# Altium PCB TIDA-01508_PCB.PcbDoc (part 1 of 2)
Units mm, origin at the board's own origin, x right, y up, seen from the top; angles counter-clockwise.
Board outline 58.5 x 103 mm, 4 copper layers (Top Layer, GND, VCC, Bottom Layer), stack 1.565 mm thick; 194 components, 119 nets, 642 pads, 130 vias.
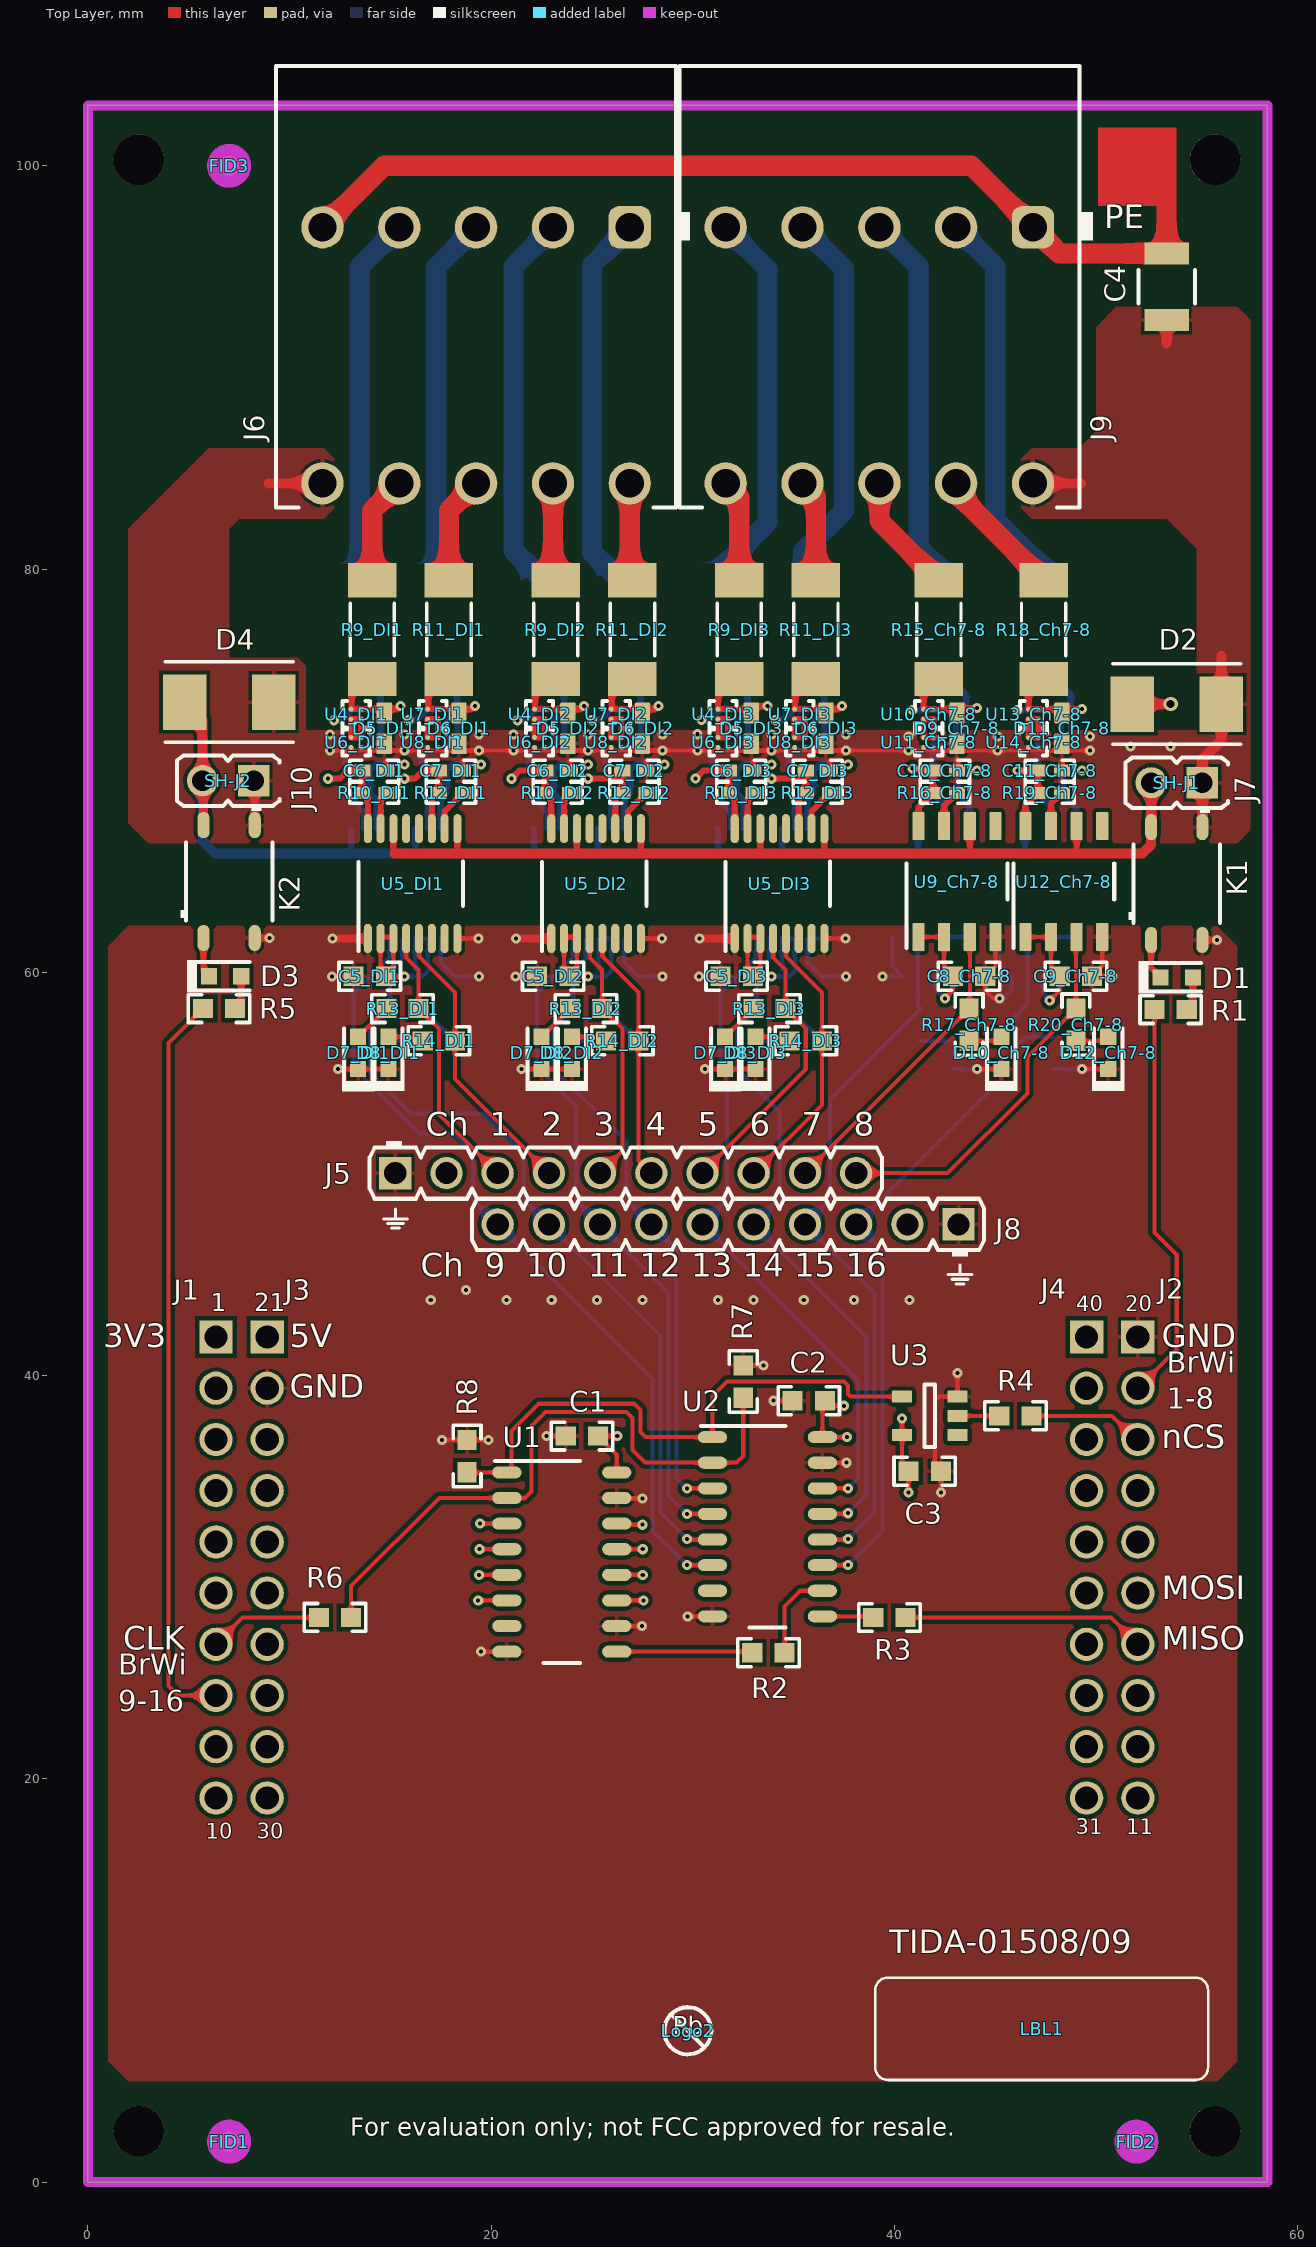
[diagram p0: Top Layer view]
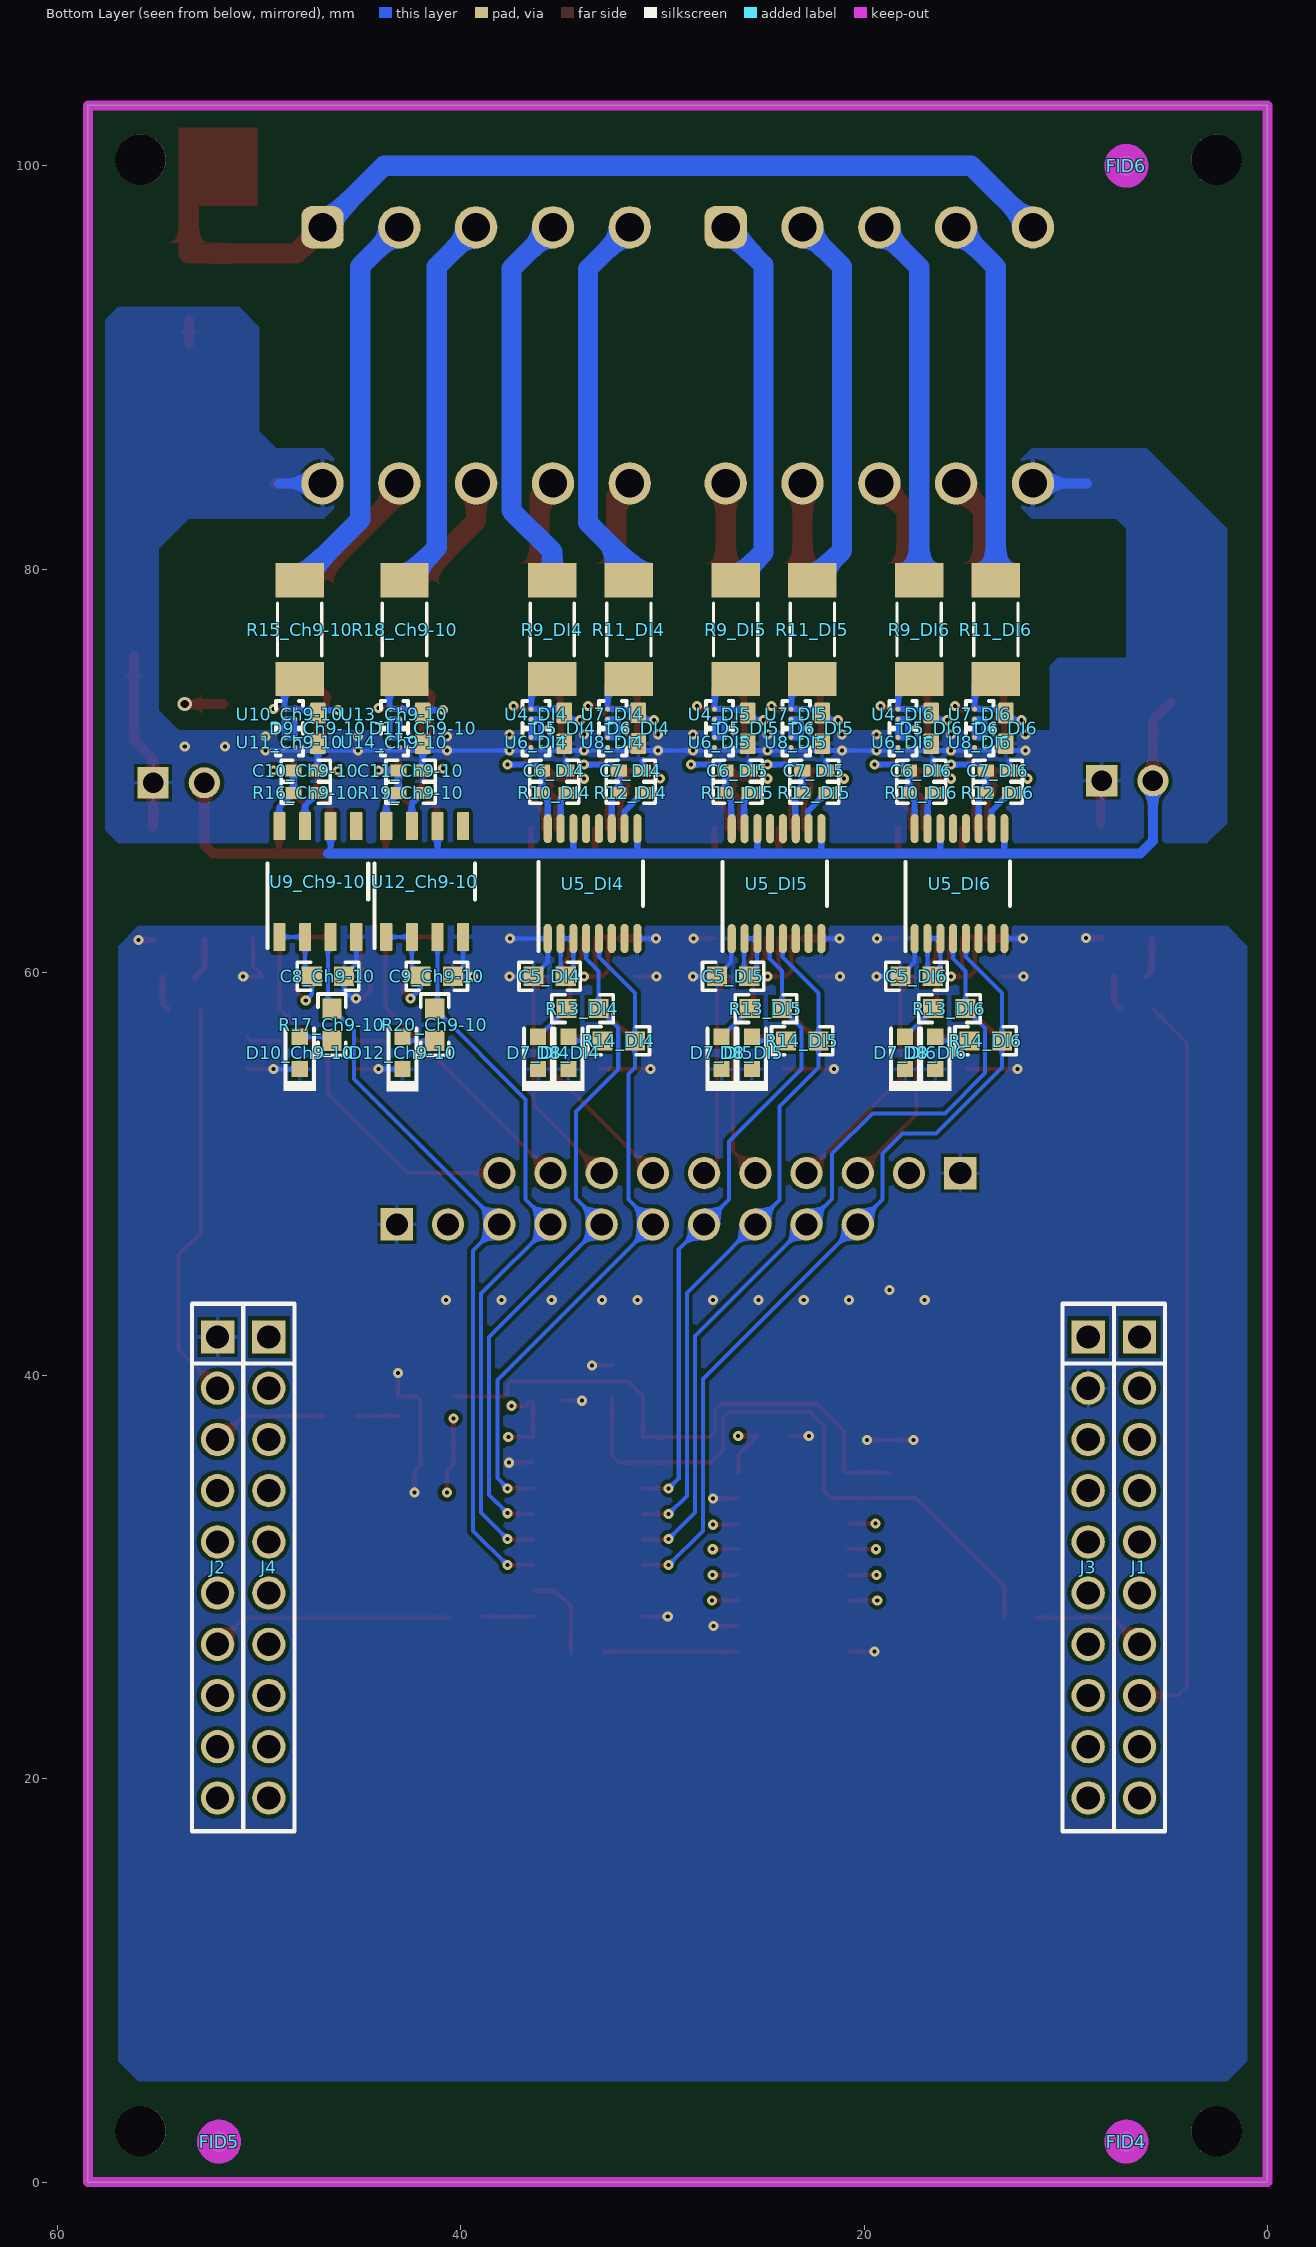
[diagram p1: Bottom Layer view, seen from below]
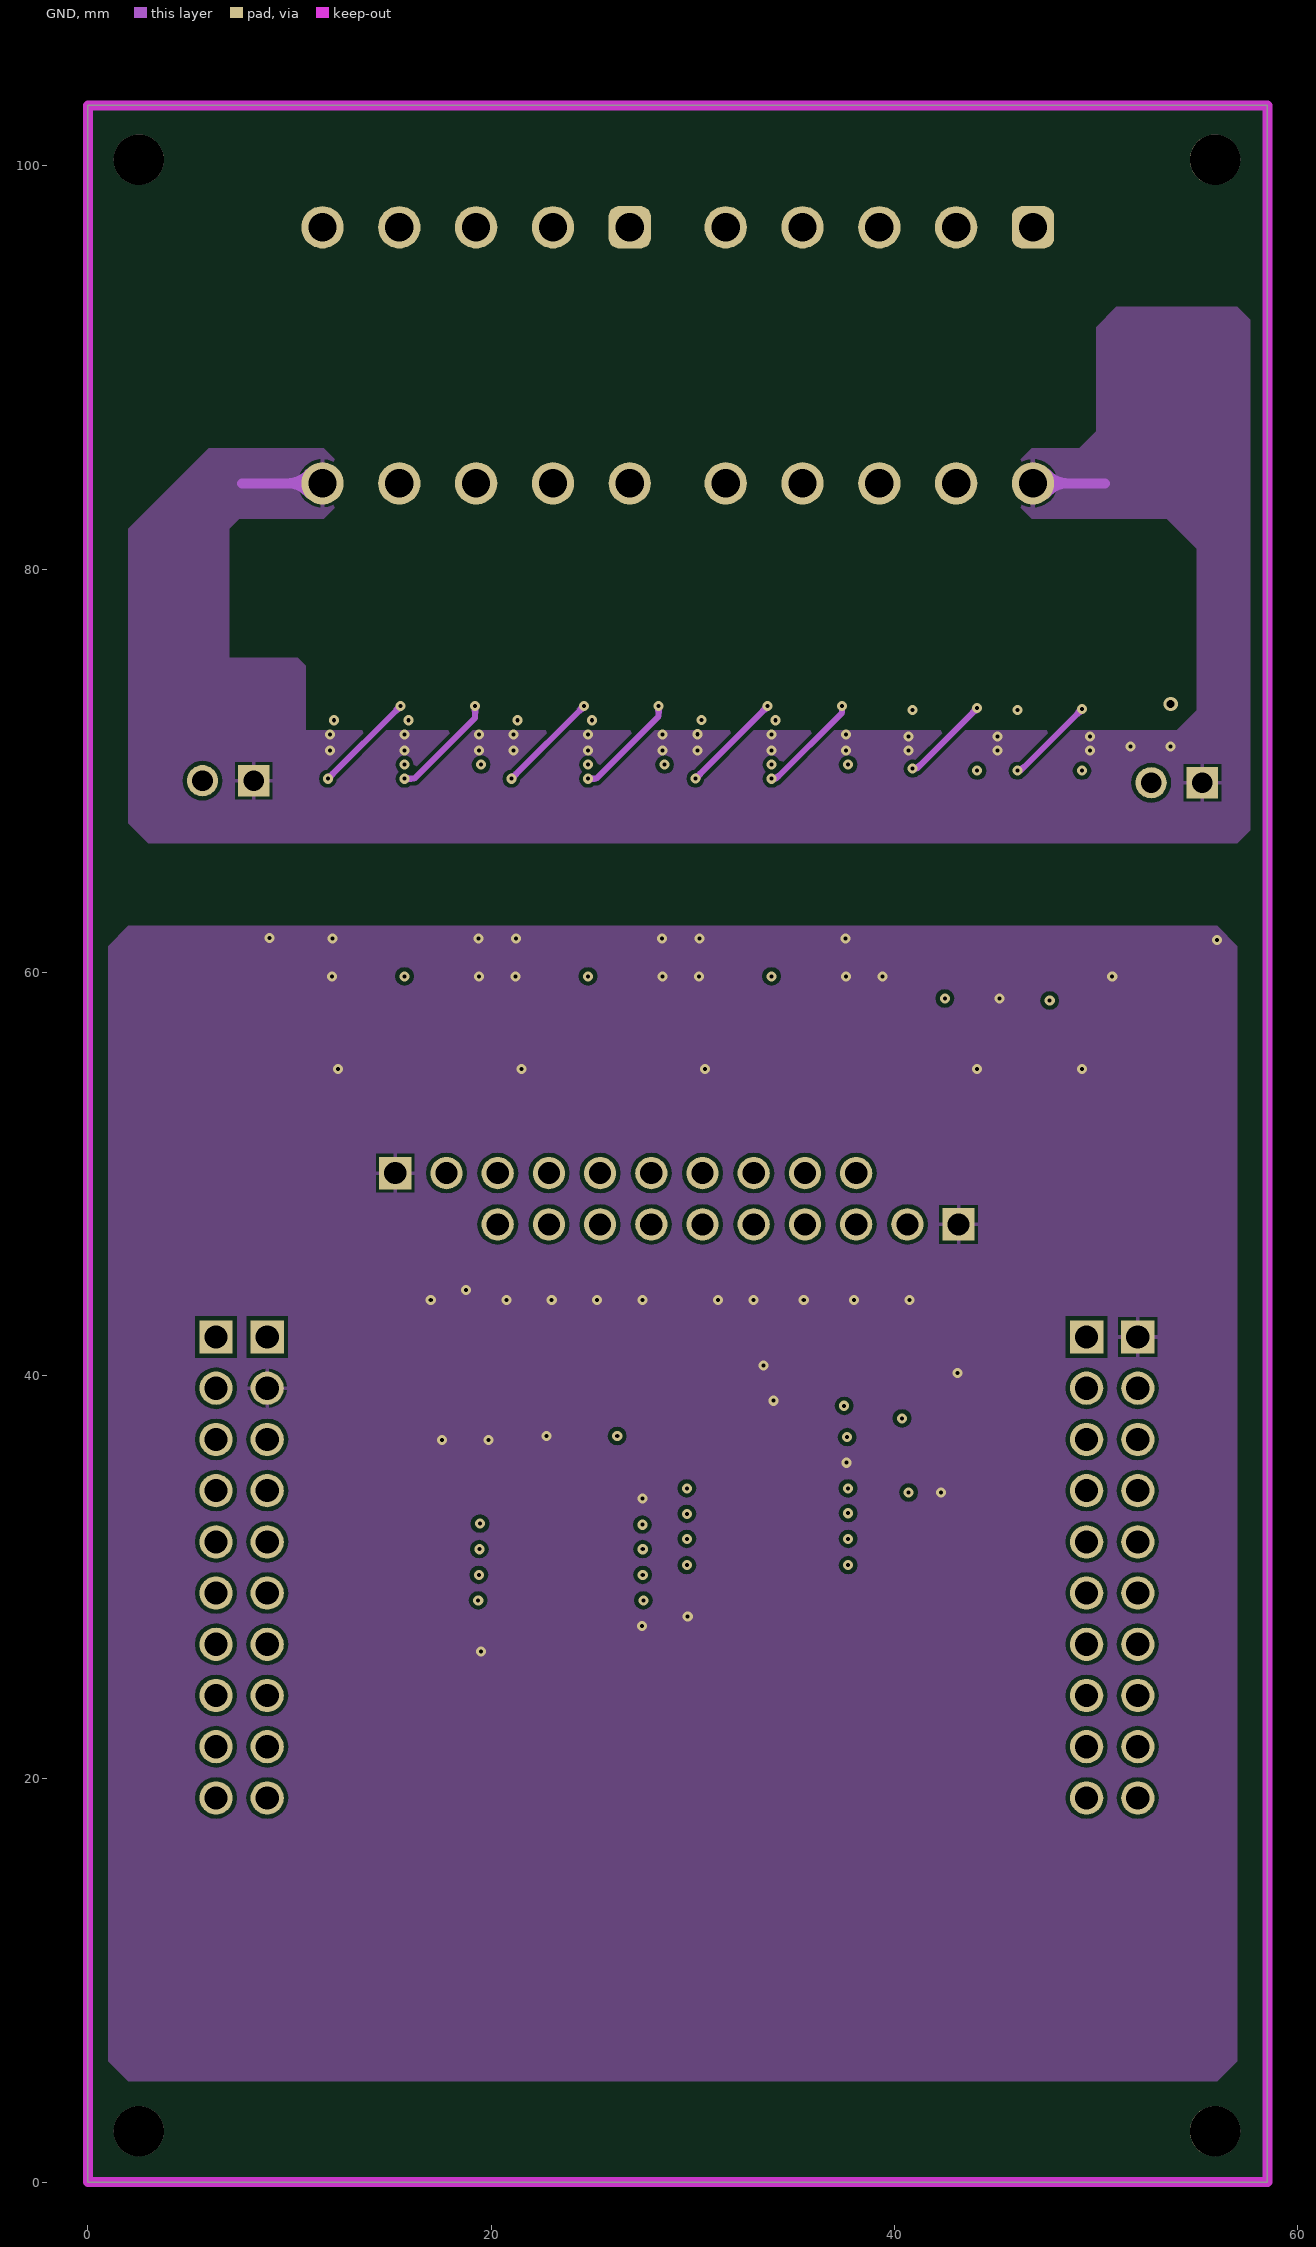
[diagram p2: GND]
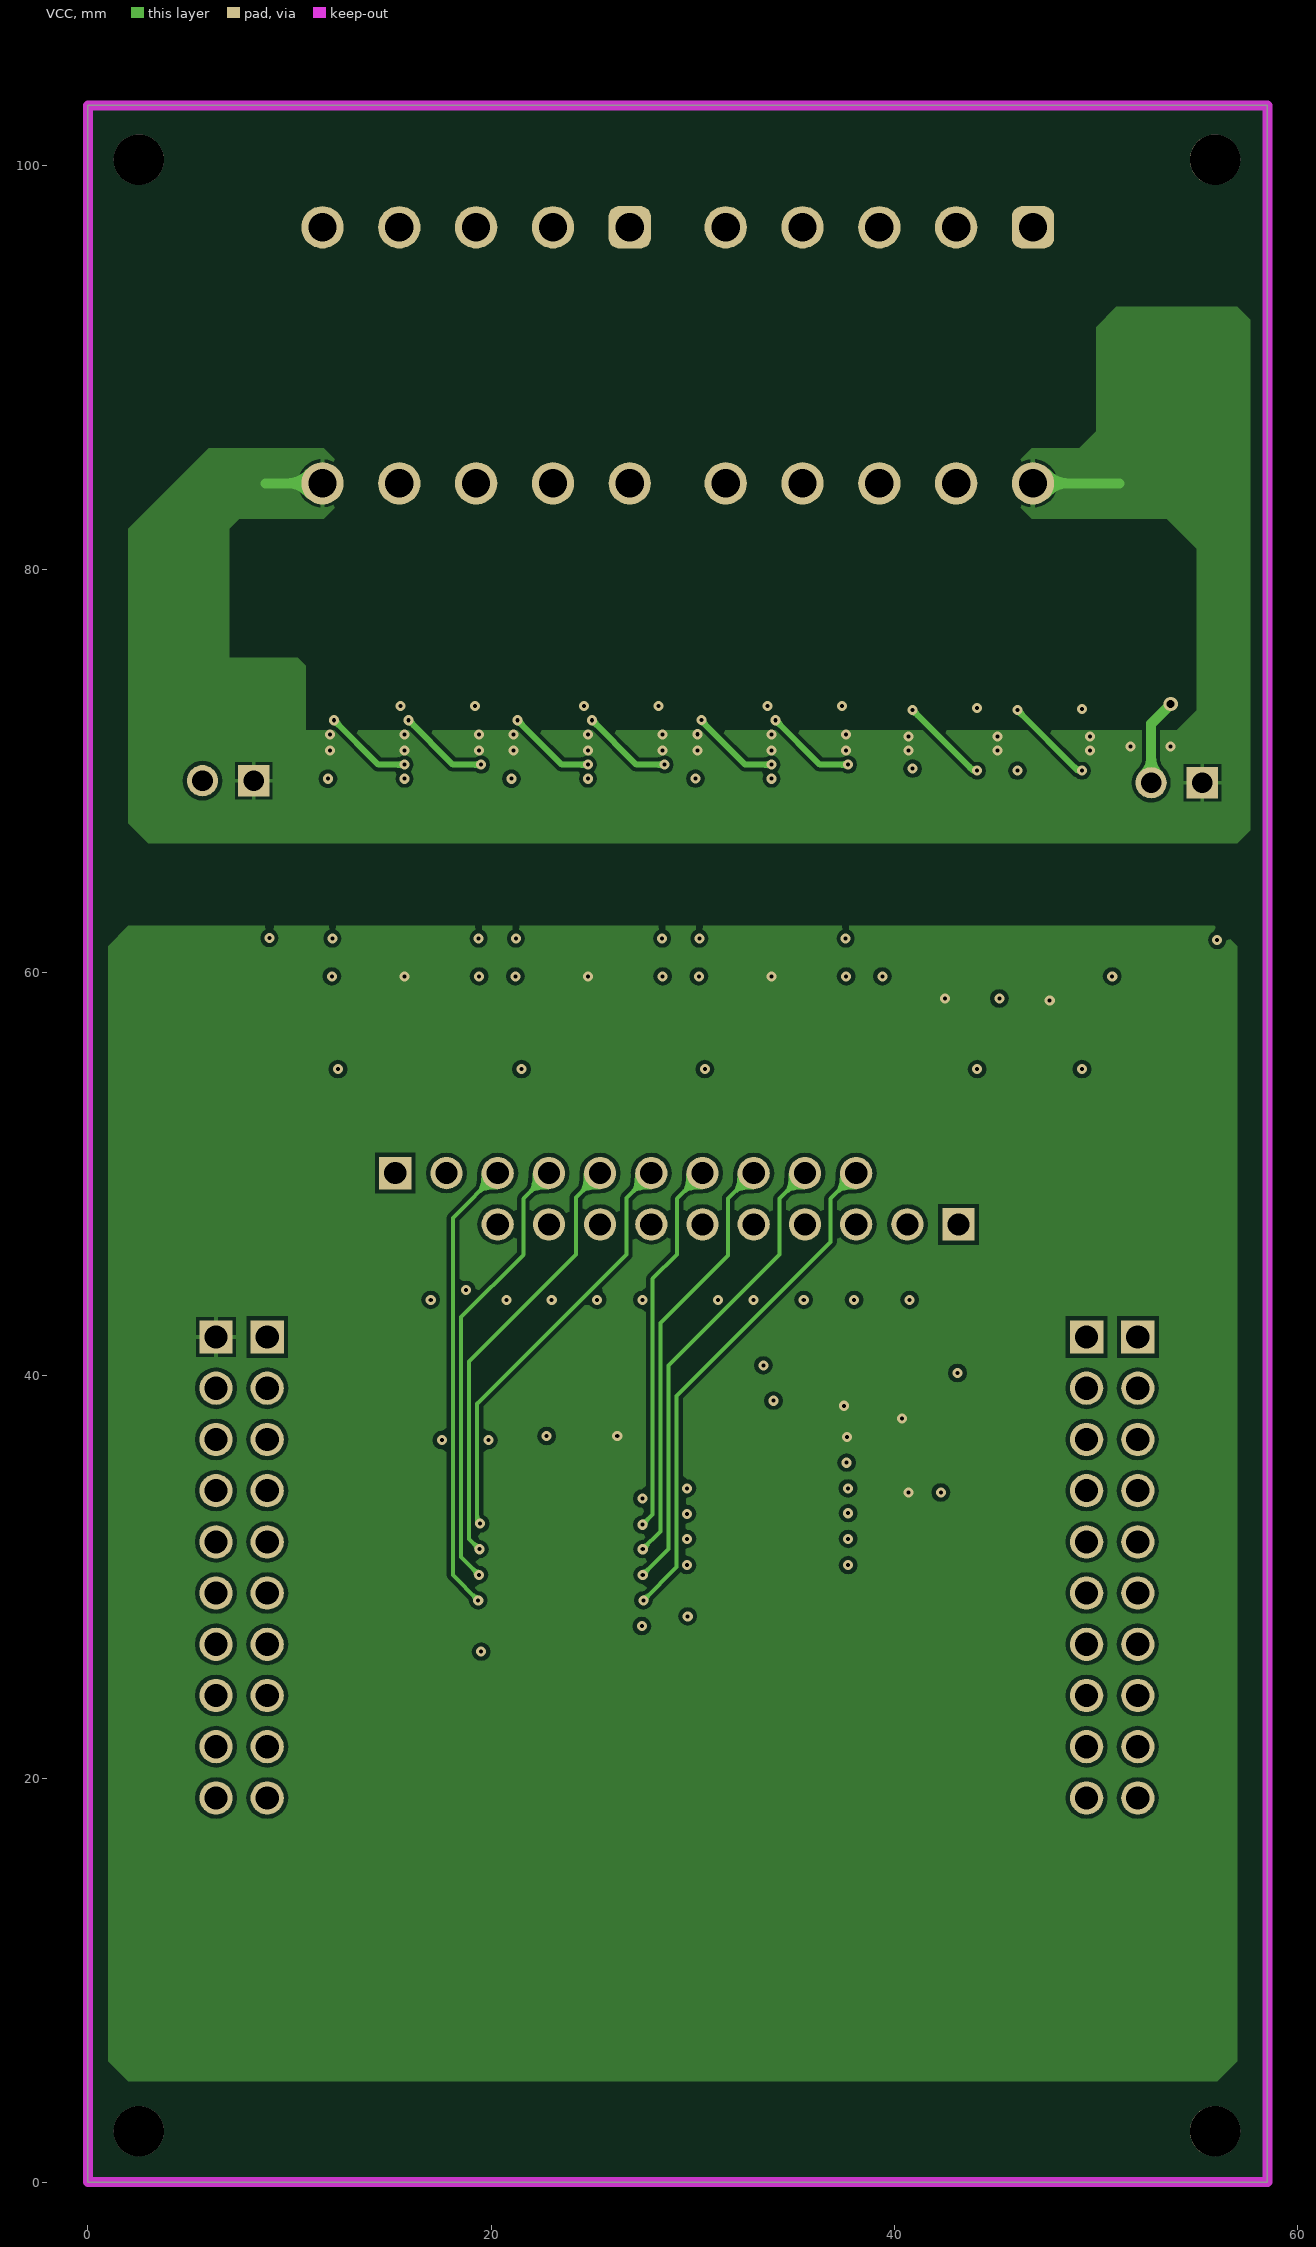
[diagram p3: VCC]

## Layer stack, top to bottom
Top Solder: solder mask 0.0102, Solder Resist, Dk 3.5
Top Layer: signal copper 0.0356
Dielectric 1: prepreg 0.2032, FR-4, Dk 4.2
GND: signal copper 0.0356
Dielectric 2: core 1.016, FR-4, Dk 4.2
VCC: signal copper 0.0356
Dielectric 3: prepreg 0.2032, FR-4, Dk 4.2
Bottom Layer: signal copper 0.0356
Bottom Solder: solder mask 0.0102, Solder Resist, Dk 3.5

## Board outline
0,0 0,103 58.5,103 58.5,0

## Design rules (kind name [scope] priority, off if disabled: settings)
AcuteAngle [All] p1: minimum=4.50000000000000E+0001 checktracksonly=FALSE
AssemblyTestPointUsage [All] p1: valid=2
Clearance Clearance_FID [IsKeepOut and InComponentClass('FiducialMark') vs IsPad and InComponentClass('FiducialMark')] p1: gap=0 ignorepadtopadclearanceinfootprint=FALSE
Clearance Clearance_Keepouts [((IsTrack Or IsArc) And Not InPoly) And IsFree and IsKeepOut vs ((IsTrack Or IsArc) And Not InPoly) And IsFree and IsKeepOut] p2: gap=0 ignorepadtopadclearanceinfootprint=FALSE
Clearance Clearance_BoardEdge_MountingHoles [OnCopper and InComponentClass('Mounting Holes') vs IsKeepOut] p3: gap=1 ignorepadtopadclearanceinfootprint=FALSE except(0: Arc-Hole Track-Hole SMDPad-Hole THPad-Hole Via-Hole Fill-Hole Poly-Hole Region-Hole Text-Hole)
Clearance Clearance_BoardEdge_Poly [OnCopper and InPoly vs IsKeepOut] p4: gap=0.6 ignorepadtopadclearanceinfootprint=FALSE except(0: Arc-Hole Track-Hole SMDPad-Hole THPad-Hole Via-Hole Fill-Hole Poly-Hole Region-Hole Text-Hole)
Clearance Clearance_BoardEdge [OnCopper and Not InComponentClass('Logo') and not InComponentClass('FiducialMark') and not InRegion(1000,500,4000,800) and Not IsKeepout vs IsKeepOut] p5: gap=0.635 ignorepadtopadclearanceinfootprint=FALSE except(0: Arc-Hole Track-Hole SMDPad-Hole THPad-Hole Via-Hole Fill-Hole Poly-Hole Region-Hole Text-Hole)
Clearance Clearance_Poly [InPolygon] p6: gap=0.2 ignorepadtopadclearanceinfootprint=FALSE except(0: Arc-Hole Track-Hole SMDPad-Hole THPad-Hole Via-Hole Fill-Hole Poly-Hole Region-Hole Text-Hole)
Clearance [All] p7: gap=0.15 ignorepadtopadclearanceinfootprint=FALSE except(0: Arc-Hole Track-Hole SMDPad-Hole THPad-Hole Via-Hole Fill-Hole Poly-Hole Region-Hole Text-Hole)
ComponentClearance ComponentClearance_Shunt [InComponentClass('Header') vs InComponentClass('Shunt')] p1: gap=0 collisioncheckmode=3 verticalgap=0 showdistances=FALSE
ComponentClearance ComponentClearance_Header2Header [InComponentClass('Header') vs InComponentClass('Header')] p2: gap=0 collisioncheckmode=3 verticalgap=0 showdistances=FALSE
ComponentClearance ComponentClearance_SmallPassives [HasFootprint('0201*') or HasFootprint('0402*') or HasFootprint('0508') or HasFootprint('0603*') or HasFootprint('0612') or HasFootprint('0805*') or HasFootprint('0815*') or HasFootprint('0830*') or HasFootprint('1206*') or HasFootprint('1210*') or HasFootprint('1808*') or HasFootprint('1812*') or HasFootprint('1825*') or HasFootprint('2010*') or HasFootprint('2220*') or HasFootprint('2225*') or HasFootprint('2512*') or HasFootprint('2728*') or HasFootprint('3518*') vs HasFootprint('0201*') or HasFootprint('0402*') or HasFootprint('0508') or HasFootprint('0603*') or HasFootprint('0612') or HasFootprint('0805*') or HasFootprint('0815*') or HasFootprint('0830*') or HasFootprint('1206*') or HasFootprint('1210*') or HasFootprint('1808*') or HasFootprint('1812*') or HasFootprint('1825*') or HasFootprint('2010*') or HasFootprint('2220*') or HasFootprint('2225*') or HasFootprint('2512*') or HasFootprint('2728*') or HasFootprint('3518*')] p3: gap=0.4 collisioncheckmode=3 verticalgap=0.254 showdistances=FALSE
ComponentClearance ComponentClearance_THtoSMT [IsThruComponent vs IsSMTComponent] p4: gap=0.5 collisioncheckmode=3 verticalgap=0.762 showdistances=FALSE
ComponentClearance ComponentClearance_MountingHoles_FiducialMarks [InComponentClass('Mounting Holes') vs InComponentClass('FiducialMark')] p5: gap=1.25 collisioncheckmode=3 verticalgap=0.254 showdistances=FALSE
ComponentClearance ComponentClearance_THtoTH [IsThruComponent vs IsThruComponent] p6: gap=1.25 collisioncheckmode=3 verticalgap=0.508 showdistances=FALSE
ComponentClearance ComponentClearance_Logo [InComponentClass('Logo')] p7: gap=1.25 collisioncheckmode=3 verticalgap=0.254 showdistances=FALSE
ComponentClearance [All] p8: gap=0.25 collisioncheckmode=3 verticalgap=0.25 showdistances=FALSE
DiffPairsRouting [All] p1: maxlimit=2.54 minlimit=0.254 mostfreqgap=0.254 toplayer_minwidth=0.381 toplayer_maxwidth=0.381 toplayer_prefwidth=0.381 midlayer1_minwidth=0.381 midlayer1_maxwidth=0.381 midlayer1_prefwidth=0.381 midlayer2_minwidth=0.381 midlayer2_maxwidth=0.381 midlayer2_prefwidth=0.381 bottomlayer_minwidth=0.381 bottomlayer_maxwidth=0.381 bottomlayer_prefwidth=0.381 maxuncoupledlength=25.4
FabricationTestPointUsage TestPointUsage [All] p1: valid=2 allowmultiple=FALSE
FabricationTestpoint Testpoint [All] p1: side=3 testpointundercomponent=TRUE minsize=1.016 maxsize=2.54 preferedsize=1.524 minholesize=0 maxholesize=1.016 preferedholesize=0.813 testpointgrid=0.025 allowsidetop=TRUE allowsidebottom=TRUE usegrid=TRUE gridtolerance=0
FanoutControl Fanout_LCC [IsLCC] p1: bgadir=Out bgaviamode=Centered fanoutstyle=Auto fanoutdirection=Alternating viagrid=0.025 // Fanout_LCC (Default Rule)
FanoutControl Fanout_BGA [IsBGA] p2: bgadir=Out bgaviamode=Centered fanoutstyle=Auto fanoutdirection=Alternating viagrid=0.025 // Fanout_BGA (Default Rule)
FanoutControl Fanout_Default [All] p4: bgadir=Out bgaviamode=Centered fanoutstyle=Auto fanoutdirection=Alternating viagrid=0.025 // Fanout_Default (Default Rule)
FanoutControl Fanout_Small [(CompPinCount < 5)] p5: bgadir=Out bgaviamode=Centered fanoutstyle=Auto fanoutdirection=OutThenIn viagrid=0.025 // Fanout_Small (Default Rule)
HoleSize [All] p1: absolutevalues=TRUE maxlimit=5 minlimit=0.2 maxpercent=80.000 minpercent=20.000
HoleToHoleClearance [All] p1: gap=0.25 allowstackedmicrovias=TRUE
MinimumAnnularRing MinimumAnnularRing_ThermalPadVias [IsVia and InAnyComponent] p1: minimumring=0.15
MinimumAnnularRing [All] p2: minimumring=0.15
MinimumSolderMaskSliver MinimumSolderMaskSliver_ISO121x [HasFootprint('DBQ0016A_N') vs HasFootprint('DBQ0016A_N')] p1: minsoldermaskwidth=0
MinimumSolderMaskSliver MinimumSolderMaskSliver_TVS3300 [HasFootprint('YZF0004-C01') vs HasFootprint('YZF0004-C01')] p2: minsoldermaskwidth=0
MinimumSolderMaskSliver MinimumSolderMaskSliver_Logo [InComponentClass('Logo') vs InComponentClass('Logo')] p3: minsoldermaskwidth=0.015
MinimumSolderMaskSliver [All] p4: minsoldermaskwidth=0.1
PlaneClearance [All] p1: clearance=0.5
PlaneConnect [All] p1: planeconnectstyle=Direct reliefexpansion=0.254 reliefentries=4 reliefconductorwidth=0.254 reliefairgap=0.254
PolygonConnect [All] p1: thpad.connectstyle=Relief thpad.reliefconductorwidth=0.2 thpad.reliefentries=4 thpad.polygonreliefangle="90 Angle" thpad.airgapwidth=0.15 smdpad.connectstyle=Relief smdpad.reliefconductorwidth=0.2 smdpad.reliefentries=4 smdpad.polygonreliefangle="90 Angle" smdpad.airgapwidth=0.15 via.connectstyle=Direct via.reliefconductorwidth=0.254 via.reliefentries=4 via.polygonreliefangle="90 Angle" via.airgapwidth=0.254
RoomDefinition DI5 [InComponentClass('DI5')] p1: confinementstyle=ConfineIn formatcopy=TRUE lockcomponents=TRUE outline 20.7,54 20.7,80.5 28.8,80.5 28.8,54
RoomDefinition DI6 [InComponentClass('DI6')] p2: confinementstyle=ConfineIn formatcopy=FALSE lockcomponents=TRUE outline 11.6,54 11.6,80.5 19.7,80.5 19.7,54
RoomDefinition DI4 [InComponentClass('DI4')] p3: confinementstyle=ConfineIn formatcopy=TRUE lockcomponents=TRUE outline 29.8,54 29.8,80.5 37.9,80.5 37.9,54
RoomDefinition DI2 [InComponentClass('DI2')] p4: confinementstyle=ConfineIn formatcopy=FALSE lockcomponents=TRUE outline 28.8,54 28.8,80.5 20.7,80.5 20.7,54
RoomDefinition DI3 [InComponentClass('DI3')] p5: confinementstyle=ConfineIn formatcopy=FALSE lockcomponents=TRUE outline 37.9,54 37.9,80.5 29.8,80.5 29.8,54
RoomDefinition DI1 [InComponentClass('DI1')] p6: confinementstyle=ConfineIn formatcopy=FALSE lockcomponents=TRUE outline 19.7,54 19.7,80.5 11.6,80.5 11.6,54
RoomDefinition Ch9-10 [InComponentClass('Ch9-10')] p7: confinementstyle=ConfineIn formatcopy=TRUE lockcomponents=FALSE outline 38.905,54 38.905,80.5 49.905,80.5 49.905,54
RoomDefinition Ch7-8 [InComponentClass('Ch7-8')] p8: confinementstyle=ConfineIn formatcopy=FALSE lockcomponents=FALSE outline 51.1,54 51.1,80.5 40.4,80.5 40.4,54
RoutingVias ThermalPadVias [IsVia and InAnyComponent] p1: holewidth=0.2 width=0.5 viastyle="Through Hole" minholewidth=0.2 minwidth=0.5 maxholewidth=1 maxwidth=1.3
RoutingVias [All] p2: holewidth=0.2 width=0.5 viastyle="Through Hole" minholewidth=0.2 minwidth=0.5 maxholewidth=0.5 maxwidth=0.8
ShortCircuit ShortCircuit_MH [InPadClass('MHclass')] p1: allowed=TRUE
ShortCircuit [All] p2: allowed=FALSE
SilkToBoardRegionClearance [Not ((IsComment or IsDesignator) And (Hide <> 'False')) and not InRegion(1000,500,4000,800)] p1:
SilkToSilkClearance SilkToSilkClearance_Pb-FreeLogo [(HasFootprint('Pb-Free_Overlay_Medium') OR HasFootprint('Pb-Free_Overlay_Small')) vs (HasFootprint('Pb-Free_Overlay_Medium') OR HasFootprint('Pb-Free_Overlay_Small'))] p1 off: silktosilkclearance=0
SilkToSilkClearance [All] p2 off: silktosilkclearance=0.127
SilkToSolderMaskClearance "Silk to Solder Mask Opening" [All] p1 off: minsilkscreentomaskgap=0.025 clearancetoexposedcopper=FALSE
SolderMaskExpansion SolderMaskExpansion_Via [IsVia] p1: expansion=0.05 soldermaskfromhole=TRUE
SolderMaskExpansion [IsComponent and not IsVia] p2: expansion=0.05
Width [All] p1: maxlimit=1 minlimit=0.15 preferedwidth=0.2 checkconnectedcopper=TRUE
12 further rules are at their usual default settings.

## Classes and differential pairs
channel class TIDA-01508_ISO1212: DI1 DI2 DI3 DI4 DI5 DI6
channel class TIDA-01508_ISO1211: Ch7-8 Ch9-10
component class Shunt: SH-J1 SH-J2
component class LaunchPadInterface: J1 J2 J3 J4
component class InputStage: C1 C2 C3 C4 D1 D2 D3 D4 J5 J6 J7 J8 J9 J10 K1 K2 R1 R2 R3 R4 R5 R6 R7 R8 SH-J1 SH-J2 U1 U2 U3
component class Header: J1 J2 J3 J4 J5 J6 J7 J8 J9 J10
component class DI6: C5_DI6 C6_DI6 C7_DI6 D5_DI6 D6_DI6 D7_DI6 D8_DI6 R9_DI6 R10_DI6 R11_DI6 R12_DI6 R13_DI6 R14_DI6 U4_DI6 U5_DI6 U6_DI6 U7_DI6 U8_DI6
component class DI5: C5_DI5 C6_DI5 C7_DI5 D5_DI5 D6_DI5 D7_DI5 D8_DI5 R9_DI5 R10_DI5 R11_DI5 R12_DI5 R13_DI5 R14_DI5 U4_DI5 U5_DI5 U6_DI5 U7_DI5 U8_DI5
component class DI4: C5_DI4 C6_DI4 C7_DI4 D5_DI4 D6_DI4 D7_DI4 D8_DI4 R9_DI4 R10_DI4 R11_DI4 R12_DI4 R13_DI4 R14_DI4 U4_DI4 U5_DI4 U6_DI4 U7_DI4 U8_DI4
component class DI3: C5_DI3 C6_DI3 C7_DI3 D5_DI3 D6_DI3 D7_DI3 D8_DI3 R9_DI3 R10_DI3 R11_DI3 R12_DI3 R13_DI3 R14_DI3 U4_DI3 U5_DI3 U6_DI3 U7_DI3 U8_DI3
component class DI2: C5_DI2 C6_DI2 C7_DI2 D5_DI2 D6_DI2 D7_DI2 D8_DI2 R9_DI2 R10_DI2 R11_DI2 R12_DI2 R13_DI2 R14_DI2 U4_DI2 U5_DI2 U6_DI2 U7_DI2 U8_DI2
component class DI1: C5_DI1 C6_DI1 C7_DI1 D5_DI1 D6_DI1 D7_DI1 D8_DI1 R9_DI1 R10_DI1 R11_DI1 R12_DI1 R13_DI1 R14_DI1 U4_DI1 U5_DI1 U6_DI1 U7_DI1 U8_DI1
component class Ch9-10: C8_Ch9-10 C9_Ch9-10 C10_Ch9-10 C11_Ch9-10 D9_Ch9-10 D10_Ch9-10 D11_Ch9-10 D12_Ch9-10 R15_Ch9-10 R16_Ch9-10 R17_Ch9-10 R18_Ch9-10 R19_Ch9-10 R20_Ch9-10 U9_Ch9-10 U10_Ch9-10 U11_Ch9-10 U12_Ch9-10 U13_Ch9-10 U14_Ch9-10
component class Ch7-8: C8_Ch7-8 C9_Ch7-8 C10_Ch7-8 C11_Ch7-8 D9_Ch7-8 D10_Ch7-8 D11_Ch7-8 D12_Ch7-8 R15_Ch7-8 R16_Ch7-8 R17_Ch7-8 R18_Ch7-8 R19_Ch7-8 R20_Ch7-8 U9_Ch7-8 U10_Ch7-8 U11_Ch7-8 U12_Ch7-8 U13_Ch7-8 U14_Ch7-8
component class Hardware: FID1 FID2 FID3 FID4 FID5 FID6 LBL1 Logo2 Logo3 ZZ1 ZZ2 ZZ3 ZZ4
component class FiducialMark: FID1 FID2 FID3 FID4 FID5 FID6
component class AssemblyNote: ZZ1 ZZ2 ZZ3 ZZ4
component class Label: LBL1

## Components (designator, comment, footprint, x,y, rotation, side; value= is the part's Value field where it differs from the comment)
C1 "GRM188R71H104KA93D" 0603 24.5,37 r180 top value=0.1uF
C2 "GRM188R71H104KA93D" 0603 35.75,38.75 r180 top value=0.1uF
C3 "GRM188R71H104KA93D" 0603 41.5,35.25 r0 top value=0.1uF
C4 "202S41W222KV4E" 1210_280 53.5,94 r90 top value=2200pF
C5_DI1 "GRM188R71H104KA93D" 0603 13.975,59.8 r180 top value=0.1uF (schematic designator C5)
C5_DI2 "GRM188R71H104KA93D" 0603 23.075,59.8 r180 top value=0.1uF (schematic designator C5)
C5_DI3 "GRM188R71H104KA93D" 0603 32.175,59.8 r180 top value=0.1uF (schematic designator C5)
C5_DI4 "GRM188R71H104KA93D" 0603 35.6,59.8 r0 bottom value=0.1uF (schematic designator C5)
C5_DI5 "GRM188R71H104KA93D" 0603 26.5,59.8 r0 bottom value=0.1uF (schematic designator C5)
C5_DI6 "GRM188R71H104KA93D" 0603 17.4,59.8 r0 bottom value=0.1uF (schematic designator C5)
C6_DI1 "CGA2B3X7R1H103K050BB" 0402 14.2,70 r180 top value=0.01uF (schematic designator C6)
C6_DI2 "CGA2B3X7R1H103K050BB" 0402 23.3,70 r180 top value=0.01uF (schematic designator C6)
C6_DI3 "CGA2B3X7R1H103K050BB" 0402 32.4,70 r180 top value=0.01uF (schematic designator C6)
C6_DI4 "CGA2B3X7R1H103K050BB" 0402 35.375,70 r0 bottom value=0.01uF (schematic designator C6)
C6_DI5 "CGA2B3X7R1H103K050BB" 0402 26.275,70 r0 bottom value=0.01uF (schematic designator C6)
C6_DI6 "CGA2B3X7R1H103K050BB" 0402 17.175,70 r0 bottom value=0.01uF (schematic designator C6)
C7_DI1 "CGA2B3X7R1H103K050BB" 0402 18,70 r180 top value=0.01uF (schematic designator C7)
C7_DI2 "CGA2B3X7R1H103K050BB" 0402 27.1,70 r180 top value=0.01uF (schematic designator C7)
C7_DI3 "CGA2B3X7R1H103K050BB" 0402 36.2,70 r180 top value=0.01uF (schematic designator C7)
C7_DI4 "CGA2B3X7R1H103K050BB" 0402 31.575,70 r0 bottom value=0.01uF (schematic designator C7)
C7_DI5 "CGA2B3X7R1H103K050BB" 0402 22.475,70 r0 bottom value=0.01uF (schematic designator C7)
C7_DI6 "CGA2B3X7R1H103K050BB" 0402 13.375,70 r0 bottom value=0.01uF (schematic designator C7)
C8_Ch7-8 "GRM188R71H104KA93D" 0603 43.7,59.8 r0 top value=0.1uF (schematic designator C8)
C8_Ch9-10 "GRM188R71H104KA93D" 0603 46.6,59.8 r180 bottom value=0.1uF (schematic designator C8)
C9_Ch7-8 "GRM188R71H104KA93D" 0603 49,59.8 r0 top value=0.1uF (schematic designator C9)
C9_Ch9-10 "GRM188R71H104KA93D" 0603 41.2,59.8 r180 bottom value=0.1uF (schematic designator C9)
C10_Ch7-8 "CGA2B3X7R1H103K050BB" 0402 42.5,70 r180 top value=0.01uF (schematic designator C10)
C10_Ch9-10 "CGA2B3X7R1H103K050BB" 0402 47.7,70 r0 bottom value=0.01uF (schematic designator C10)
C11_Ch7-8 "CGA2B3X7R1H103K050BB" 0402 47.7,70 r180 top value=0.01uF (schematic designator C11)
C11_Ch9-10 "CGA2B3X7R1H103K050BB" 0402 42.5,70 r0 bottom value=0.01uF (schematic designator C11)
D1 "150060RS75000" WL-SMCW_RED 54,59.75 r0 top value=Red
D2 "SM6T36CA" SMB-Bi 54,73.3 r180 top value=36V
D3 "150060RS75000" WL-SMCW_RED 6.8,59.8 r0 top value=Red
D4 "SM6T36CA" SMB-Bi 7,73.4 r180 top value=36V
D5_DI1 "CGA0603MLA-31900E" Bourns_CGA0603MLA 14.7,72.1 r90 top (schematic designator D5)
D5_DI2 "CGA0603MLA-31900E" Bourns_CGA0603MLA 23.8,72.1 r90 top (schematic designator D5)
D5_DI3 "CGA0603MLA-31900E" Bourns_CGA0603MLA 32.9,72.1 r90 top (schematic designator D5)
D5_DI4 "CGA0603MLA-31900E" Bourns_CGA0603MLA 34.875,72.1 r90 bottom (schematic designator D5)
D5_DI5 "CGA0603MLA-31900E" Bourns_CGA0603MLA 25.775,72.1 r90 bottom (schematic designator D5)
D5_DI6 "CGA0603MLA-31900E" Bourns_CGA0603MLA 16.675,72.1 r90 bottom (schematic designator D5)
D6_DI1 "CGA0603MLA-31900E" Bourns_CGA0603MLA 18.4,72.1 r90 top (schematic designator D6)
D6_DI2 "CGA0603MLA-31900E" Bourns_CGA0603MLA 27.5,72.1 r90 top (schematic designator D6)
D6_DI3 "CGA0603MLA-31900E" Bourns_CGA0603MLA 36.6,72.1 r90 top (schematic designator D6)
D6_DI4 "CGA0603MLA-31900E" Bourns_CGA0603MLA 31.202,72.106 r90 bottom (schematic designator D6)
D6_DI5 "CGA0603MLA-31900E" Bourns_CGA0603MLA 22.075,72.1 r90 bottom (schematic designator D6)
D6_DI6 "CGA0603MLA-31900E" Bourns_CGA0603MLA 12.975,72.1 r90 bottom (schematic designator D6)
D7_DI1 "150060YS75000" WL-SMCW_YELLOW 13.4,56 r90 top value=Yellow (schematic designator D7)
D7_DI2 "150060YS75000" WL-SMCW_YELLOW 22.5,56 r90 top value=Yellow (schematic designator D7)
D7_DI3 "150060YS75000" WL-SMCW_YELLOW 31.6,56 r90 top value=Yellow (schematic designator D7)
D7_DI4 "150060YS75000" WL-SMCW_YELLOW 36.175,56 r90 bottom value=Yellow (schematic designator D7)
D7_DI5 "150060YS75000" WL-SMCW_YELLOW 27.075,56 r90 bottom value=Yellow (schematic designator D7)
D7_DI6 "150060YS75000" WL-SMCW_YELLOW 17.975,56 r90 bottom value=Yellow (schematic designator D7)
D8_DI1 "150060YS75000" WL-SMCW_YELLOW 14.9,56 r90 top value=Yellow (schematic designator D8)
D8_DI2 "150060YS75000" WL-SMCW_YELLOW 24,56 r90 top value=Yellow (schematic designator D8)
D8_DI3 "150060YS75000" WL-SMCW_YELLOW 33.1,56 r90 top value=Yellow (schematic designator D8)
D8_DI4 "150060YS75000" WL-SMCW_YELLOW 34.675,56 r90 bottom value=Yellow (schematic designator D8)
D8_DI5 "150060YS75000" WL-SMCW_YELLOW 25.575,56 r90 bottom value=Yellow (schematic designator D8)
D8_DI6 "150060YS75000" WL-SMCW_YELLOW 16.475,56 r90 bottom value=Yellow (schematic designator D8)
D9_Ch7-8 "CGA0603MLA-31900E" Bourns_CGA0603MLA 43.1,72.1 r90 top (schematic designator D9)
D9_Ch9-10 "CGA0603MLA-31900E" Bourns_CGA0603MLA 47.1,72.1 r90 bottom (schematic designator D9)
D10_Ch7-8 "150060YS75000" WL-SMCW_YELLOW 45.3,56 r90 top value=Yellow (schematic designator D10)
D10_Ch9-10 "150060YS75000" WL-SMCW_YELLOW 48,56 r90 bottom value=Yellow (schematic designator D10)
D11_Ch7-8 "CGA0603MLA-31900E" Bourns_CGA0603MLA 48.3,72.1 r90 top (schematic designator D11)
D11_Ch9-10 "CGA0603MLA-31900E" Bourns_CGA0603MLA 41.9,72.1 r90 bottom (schematic designator D11)
D12_Ch7-8 "150060YS75000" WL-SMCW_YELLOW 50.6,56 r90 top value=Yellow (schematic designator D12)
D12_Ch9-10 "150060YS75000" WL-SMCW_YELLOW 42.9,56 r90 bottom value=Yellow (schematic designator D12)
FID1 "Fiducial" Fiducial10-20 7,2 r0 top
FID2 "Fiducial" Fiducial10-20 52,2 r0 top
FID3 "Fiducial" Fiducial10-20 7,100 r0 top
FID4 "Fiducial" Fiducial10-20 7,2 r180 bottom
FID5 "Fiducial" Fiducial10-20 52,2 r180 bottom
FID6 "Fiducial" Fiducial10-20 7,100 r180 bottom
J1 "SSW-110-23-F-S" CONN_SSW-110-23-F-S 6.35,30.48 r90 bottom locked
J2 "SSW-110-23-F-S" CONN_SSW-110-23-F-S 52.07,30.48 r90 bottom locked
J3 "SSW-110-23-F-S" CONN_SSW-110-23-F-S 8.89,30.48 r90 bottom locked
J4 "SSW-110-23-F-S" CONN_SSW-110-23-F-S 49.53,30.48 r90 bottom locked
J5 "61301011121" Wurth_61301011121 26.67,50.038 r0 top
J6 "691356310010B" Wurth_691356310010B 19.25,90.6 r270 top
J7 "0022284023" Molex_0022284023 54,69.4 r180 top
J8 "61301011121" Wurth_61301011121 31.75,47.498 r180 top
J9 "691356310010B" Wurth_691356310010B 39.25,90.6 r270 top
J10 "0022284023" Molex_0022284023 6.95,69.5 r180 top
K1 "CPC1117N" RELAY_CPC1017N 54,64.4 r90 top
K2 "CPC1117N" RELAY_CPC1017N 7,64.5 r90 top
LBL1 "Size: 0.65\" x 0.20 \"" Label_650x200 47.3,7.6 r0 top
Logo2 "Pb-Free Symbol" Pb-Free_Overlay_Small 29.75,7.5 r0 top
Logo3 "FCC disclaimer" FCC_disclaimer 149,19.75 r90 top
R1 "CRCW0603100RFKEA" 0603 53.7,58.15 r0 top value=100
R2 "CRCW060347R0JNEA" 0603 33.75,26.25 r180 top value=47
R3 "CRCW060347R0JNEA" 0603 39.75,28 r180 top value=47
R4 "CRCW06030000Z0EA" 0603 46,38 r180 top value=0
R5 "CRCW0603100RFKEA" 0603 6.5,58.2 r0 top value=100
R6 "CRCW06030000Z0EA" 0603 12.25,28 r0 top value=0
R7 "CRCW0603100RFKEA" 0603 32.5,39.7 r270 top value=100
R8 "CRCW0603100RFKEA" 0603 18.8,36 r270 top value=100
R9_DI1 "MMB02070C2491FB200" MMB0207 14.1,77 r90 top value=2.49k (schematic designator R9)
R9_DI2 "MMB02070C2491FB200" MMB0207 23.2,77 r90 top value=2.49k (schematic designator R9)
R9_DI3 "MMB02070C2491FB200" MMB0207 32.3,77 r90 top value=2.49k (schematic designator R9)
R9_DI4 "MMB02070C2491FB200" MMB0207 35.475,77 r90 bottom value=2.49k (schematic designator R9)
R9_DI5 "MMB02070C2491FB200" MMB0207 26.375,77 r90 bottom value=2.49k (schematic designator R9)
R9_DI6 "MMB02070C2491FB200" MMB0207 17.275,77 r90 bottom value=2.49k (schematic designator R9)
R10_DI1 "CRCW0402562RFKED" 0402 14.2,68.9 r180 top value=562 (schematic designator R10)
R10_DI2 "CRCW0402562RFKED" 0402 23.3,68.9 r180 top value=562 (schematic designator R10)
R10_DI3 "CRCW0402562RFKED" 0402 32.4,68.9 r180 top value=562 (schematic designator R10)
R10_DI4 "CRCW0402562RFKED" 0402 35.375,68.9 r0 bottom value=562 (schematic designator R10)
R10_DI5 "CRCW0402562RFKED" 0402 26.275,68.9 r0 bottom value=562 (schematic designator R10)
R10_DI6 "CRCW0402562RFKED" 0402 17.175,68.9 r0 bottom value=562 (schematic designator R10)
R11_DI1 "MMB02070C2491FB200" MMB0207 17.9,77 r90 top value=2.49k (schematic designator R11)
R11_DI2 "MMB02070C2491FB200" MMB0207 27,77 r90 top value=2.49k (schematic designator R11)
R11_DI3 "MMB02070C2491FB200" MMB0207 36.1,77 r90 top value=2.49k (schematic designator R11)
R11_DI4 "MMB02070C2491FB200" MMB0207 31.675,77 r90 bottom value=2.49k (schematic designator R11)
R11_DI5 "MMB02070C2491FB200" MMB0207 22.575,77 r90 bottom value=2.49k (schematic designator R11)
R11_DI6 "MMB02070C2491FB200" MMB0207 13.475,77 r90 bottom value=2.49k (schematic designator R11)
R12_DI1 "CRCW0402562RFKED" 0402 18,68.9 r180 top value=562 (schematic designator R12)
R12_DI2 "CRCW0402562RFKED" 0402 27.1,68.9 r180 top value=562 (schematic designator R12)
R12_DI3 "CRCW0402562RFKED" 0402 36.2,68.9 r180 top value=562 (schematic designator R12)
R12_DI4 "CRCW0402562RFKED" 0402 31.575,68.9 r0 bottom value=562 (schematic designator R12)
R12_DI5 "CRCW0402562RFKED" 0402 22.475,68.9 r0 bottom value=562 (schematic designator R12)
R12_DI6 "CRCW0402562RFKED" 0402 13.375,68.9 r0 bottom value=562 (schematic designator R12)
R13_DI1 "CRCW0603750RFKEA" 0603 15.6,58.2 r0 top value=750 (schematic designator R13)
R13_DI2 "CRCW0603750RFKEA" 0603 24.7,58.2 r0 top value=750 (schematic designator R13)
R13_DI3 "CRCW0603750RFKEA" 0603 33.8,58.2 r0 top value=750 (schematic designator R13)
R13_DI4 "CRCW0603750RFKEA" 0603 33.975,58.2 r180 bottom value=750 (schematic designator R13)
R13_DI5 "CRCW0603750RFKEA" 0603 24.875,58.2 r180 bottom value=750 (schematic designator R13)
R13_DI6 "CRCW0603750RFKEA" 0603 15.775,58.2 r180 bottom value=750 (schematic designator R13)
R14_DI1 "CRCW0603750RFKEA" 0603 17.4,56.6 r0 top value=750 (schematic designator R14)
R14_DI2 "CRCW0603750RFKEA" 0603 26.5,56.6 r0 top value=750 (schematic designator R14)
R14_DI3 "CRCW0603750RFKEA" 0603 35.6,56.6 r0 top value=750 (schematic designator R14)
R14_DI4 "CRCW0603750RFKEA" 0603 32.175,56.6 r180 bottom value=750 (schematic designator R14)
R14_DI5 "CRCW0603750RFKEA" 0603 23.075,56.6 r180 bottom value=750 (schematic designator R14)
R14_DI6 "CRCW0603750RFKEA" 0603 13.975,56.6 r180 bottom value=750 (schematic designator R14)
R15_Ch7-8 "MMB02070C2491FB200" MMB0207 42.2,77 r90 top value=2.49k (schematic designator R15)
R15_Ch9-10 "MMB02070C2491FB200" MMB0207 48,77 r90 bottom value=2.49k (schematic designator R15)
R16_Ch7-8 "CRCW0402562RFKED" 0402 42.5,68.9 r180 top value=562 (schematic designator R16)
R16_Ch9-10 "CRCW0402562RFKED" 0402 47.7,68.9 r0 bottom value=562 (schematic designator R16)
R17_Ch7-8 "CRCW0603750RFKEA" 0603 43.7,57.4 r90 top value=750 (schematic designator R17)
R17_Ch9-10 "CRCW0603750RFKEA" 0603 46.4,57.4 r90 bottom value=750 (schematic designator R17)
R18_Ch7-8 "MMB02070C2491FB200" MMB0207 47.4,77 r90 top value=2.49k (schematic designator R18)
R18_Ch9-10 "MMB02070C2491FB200" MMB0207 42.8,77 r90 bottom value=2.49k (schematic designator R18)
R19_Ch7-8 "CRCW0402562RFKED" 0402 47.7,68.9 r180 top value=562 (schematic designator R19)
R19_Ch9-10 "CRCW0402562RFKED" 0402 42.5,68.9 r0 bottom value=562 (schematic designator R19)
R20_Ch7-8 "CRCW0603750RFKEA" 0603 49,57.4 r90 top value=750 (schematic designator R20)
R20_Ch9-10 "CRCW0603750RFKEA" 0603 41.3,57.4 r90 bottom value=750 (schematic designator R20)
SH-J1 "60900213421" Wurth_60900213421 54,69.4 r180 top
SH-J2 "60900213421" Wurth_60900213421 6.95,69.5 r180 top
U1 "SN74LV165AD" D0016A_N 23.5,30.75 r0 top
U2 "SN74LV165AD" D0016A_N 33.7,32.5 r0 top
U3 "SN74LVC1GU04DBVR" DBV0005A_N 41.75,38 r180 top
U4_DI1 "TVS3300YZFR" YZF0004-C01 13.3,72.8 r0 top (schematic designator U4)
U4_DI2 "TVS3300YZFR" YZF0004-C01 22.4,72.8 r0 top (schematic designator U4)
U4_DI3 "TVS3300YZFR" YZF0004-C01 31.5,72.8 r0 top (schematic designator U4)
U4_DI4 "TVS3300YZFR" YZF0004-C01 36.275,72.8 r180 bottom (schematic designator U4)
U4_DI5 "TVS3300YZFR" YZF0004-C01 27.175,72.8 r180 bottom (schematic designator U4)
U4_DI6 "TVS3300YZFR" YZF0004-C01 18.075,72.8 r180 bottom (schematic designator U4)
U5_DI1 "ISO1212DBQR" DBQ0016A_N 16.1,64.4 r90 top (schematic designator U5)
U5_DI2 "ISO1212DBQR" DBQ0016A_N 25.2,64.4 r90 top (schematic designator U5)
U5_DI3 "ISO1212DBQR" DBQ0016A_N 34.3,64.4 r90 top (schematic designator U5)
U5_DI4 "ISO1212DBQR" DBQ0016A_N 33.475,64.4 r90 bottom (schematic designator U5)
U5_DI5 "ISO1212DBQR" DBQ0016A_N 24.348,64.394 r90 bottom (schematic designator U5)
U5_DI6 "ISO1212DBQR" DBQ0016A_N 15.275,64.4 r90 bottom (schematic designator U5)
U6_DI1 "TVS3300YZFR" YZF0004-C01 13.3,71.4 r180 top (schematic designator U6)
U6_DI2 "TVS3300YZFR" YZF0004-C01 22.4,71.4 r180 top (schematic designator U6)
U6_DI3 "TVS3300YZFR" YZF0004-C01 31.5,71.4 r180 top (schematic designator U6)
U6_DI4 "TVS3300YZFR" YZF0004-C01 36.275,71.4 r0 bottom (schematic designator U6)
U6_DI5 "TVS3300YZFR" YZF0004-C01 27.175,71.4 r0 bottom (schematic designator U6)
U6_DI6 "TVS3300YZFR" YZF0004-C01 18.075,71.4 r0 bottom (schematic designator U6)
U7_DI1 "TVS3300YZFR" YZF0004-C01 17.1,72.8 r0 top (schematic designator U7)
U7_DI2 "TVS3300YZFR" YZF0004-C01 26.2,72.8 r0 top (schematic designator U7)
U7_DI3 "TVS3300YZFR" YZF0004-C01 35.3,72.8 r0 top (schematic designator U7)
U7_DI4 "TVS3300YZFR" YZF0004-C01 32.475,72.8 r180 bottom (schematic designator U7)
U7_DI5 "TVS3300YZFR" YZF0004-C01 23.375,72.8 r180 bottom (schematic designator U7)
U7_DI6 "TVS3300YZFR" YZF0004-C01 14.275,72.8 r180 bottom (schematic designator U7)
U8_DI1 "TVS3300YZFR" YZF0004-C01 17.1,71.4 r180 top (schematic designator U8)
U8_DI2 "TVS3300YZFR" YZF0004-C01 26.2,71.4 r180 top (schematic designator U8)
U8_DI3 "TVS3300YZFR" YZF0004-C01 35.3,71.4 r180 top (schematic designator U8)
U8_DI4 "TVS3300YZFR" YZF0004-C01 32.475,71.4 r0 bottom (schematic designator U8)
U8_DI5 "TVS3300YZFR" YZF0004-C01 23.375,71.4 r0 bottom (schematic designator U8)
U8_DI6 "TVS3300YZFR" YZF0004-C01 14.275,71.4 r0 bottom (schematic designator U8)
U9_Ch7-8 "ISO1211DR" D0008B_HV 43.1,64.5 r90 top (schematic designator U9)
U9_Ch9-10 "ISO1211DR" D0008B_HV 47.1,64.5 r90 bottom (schematic designator U9)
U10_Ch7-8 "TVS3300YZFR" YZF0004-C01 41.7,72.8 r0 top (schematic designator U10)
U10_Ch9-10 "TVS3300YZFR" YZF0004-C01 48.5,72.8 r180 bottom (schematic designator U10)
U11_Ch7-8 "TVS3300YZFR" YZF0004-C01 41.7,71.4 r180 top (schematic designator U11)
U11_Ch9-10 "TVS3300YZFR" YZF0004-C01 48.5,71.4 r0 bottom (schematic designator U11)
U12_Ch7-8 "ISO1211DR" D0008B_HV 48.4,64.5 r90 top (schematic designator U12)
U12_Ch9-10 "ISO1211DR" D0008B_HV 41.8,64.5 r90 bottom (schematic designator U12)
U13_Ch7-8 "TVS3300YZFR" YZF0004-C01 46.9,72.8 r0 top (schematic designator U13)
U13_Ch9-10 "TVS3300YZFR" YZF0004-C01 43.3,72.8 r180 bottom (schematic designator U13)
U14_Ch7-8 "TVS3300YZFR" YZF0004-C01 46.9,71.4 r180 top (schematic designator U14)
U14_Ch9-10 "TVS3300YZFR" YZF0004-C01 43.3,71.4 r0 bottom (schematic designator U14)
ZZ1 "This Assembly Note is for PCB labels only" AssemblyNoteLabel 2.54,118.567 r0 top
ZZ2 "This Assembly Note will show in the PcbDoc and associated outputs" AssemblyNote 2.54,115.801 r0 top
ZZ3 "This Assembly Note will show in the PcbDoc and associated outputs" AssemblyNote 2.54,113.552 r0 top
ZZ4 "This Assembly Note will show in the PcbDoc and associated outputs" AssemblyNote 2.54,111.303 r0 top

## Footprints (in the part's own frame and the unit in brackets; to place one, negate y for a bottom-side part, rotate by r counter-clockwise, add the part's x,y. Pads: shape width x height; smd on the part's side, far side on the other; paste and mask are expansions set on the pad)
0402 [mm] "0402 from SM-752 data"
  rect 0.8x0.6 smd: 1(-0.6,0) 2(0.6,0)
  silkscreen extent -1.22,-0.52 1.22,0.52, body extent -0.55,-0.3 0.55,0.3, height 0.6
0603 [mm] "0603 from SM-752 data"
  rect 1x0.95 smd: 1(-0.8,0) 2(0.8,0)
  silkscreen extent -1.52,-0.69 1.52,0.69, body extent -0.87,-0.47 0.87,0.47, height 1
1210_280 [mm] "SMD, 2-Leads, Body 3.6x2.8mm, Height 2.8mm"
  rect 1.1x2.2 smd: 1(-1.65,0) 2(1.65,0)
  silkscreen extent -0.84,-1.4 0.84,1.4, body extent -1.8,-1.4 1.8,1.4, height 2.8
AssemblyNote [mm] "Assembly Note"
AssemblyNoteLabel [mm] "Assembly Note for PCB Labels"
Bourns_CGA0603MLA [mm] "SMD, 2-Leads, Body 1.6x0.8mm"
  rrect13% 1.02x0.76 smd: 1(-0.76,0) 2(0.76,0)
  body extent -0.8,-0.4 0.8,0.4, height 0.8
CONN_SSW-110-23-F-S [mm] "SAMTEC"
  rect 1.65x1.65 hole 1.15: 1(11.43,0)
  round 1.65 hole 1.15: 2(8.89,0) 3(6.35,0) 4(3.81,0) 5(1.27,0) 6(-1.27,0) 7(-3.81,0) 8(-6.35,0) 9(-8.89,0) 10(-11.43,0)
  silkscreen extent -13.08,-1.27 13.08,1.27, body extent -13,-1.27 13,1.27, height 8.59
D0008B_HV [mm] "SOIC, 8-Leads, Body 4.9x3.9mm, Pitch 1.27mm, HV / Isolation option"
  rrect17% 1.4x0.6 smd: 1(-2.75,1.905) 2(-2.75,0.635) 3(-2.75,-0.635) 4(-2.75,-1.905) 5(2.75,-1.905) 6(2.75,-0.635) 7(2.75,0.635) 8(2.75,1.905)
  silkscreen extent -3.3,-2.5 0.9,2.5, body extent -3,-2.45 3,2.45, height 1.63
D0016A_N [mm] "SOIC, 16-Leads, Body 9.9x3.9mm, Pitch 1.27mm, IPC Medium Density"
  oval 1.45x0.6 smd: 1(-2.725,4.445) 2(-2.725,3.175) 3(-2.725,1.905) 4(-2.725,0.635) 5(-2.725,-0.635) 6(-2.725,-1.905) 7(-2.725,-3.175) 8(-2.725,-4.445) 9(2.725,-4.445) 10(2.725,-3.175) 11(2.725,-1.905) 12(2.725,-0.635) 13(2.725,0.635) 14(2.725,1.905) 15(2.725,3.175) 16(2.725,4.445)
  silkscreen extent -3.3,-5 0.9,5, body extent -3,-4.95 3,4.95, height 1.6
DBQ0016A_N [mm] "SOP, 16-Leads, Body 4.9x3.9mm, Pitch 0.635mm, IPC Medium Density"
  oval 1.45x0.4 smd: 1(-2.725,2.222) 2(-2.725,1.587) 3(-2.725,0.952) 4(-2.725,0.317) 5(-2.725,-0.318) 6(-2.725,-0.953) 7(-2.725,-1.588) 8(-2.725,-2.222) 9(2.725,-2.222) 10(2.725,-1.587) 11(2.725,-0.952) 12(2.725,-0.317) 13(2.725,0.318) 14(2.725,0.953) 15(2.725,1.588) 16(2.725,2.222)
  silkscreen extent -3.35,-2.5 1.1,2.68, body extent -3.01,-2.45 3.01,2.45, height 1.63
DBV0005A_N [mm] "SOT23, 5-Leads, Body 2.9x1.6mm, Pitch 0.95mm, Lead Span 2.8mm, IPC Medium Density"
  rrect17% 1x0.6 smd: 1(-1.375,0.95) 2(-1.375,0) 3(-1.375,-0.95) 4(1.375,-0.95) 5(1.375,0.95)
  silkscreen extent -0.25,-1.55 0.25,1.55, body extent -1.42,-1.46 1.42,1.46, height 1.09
FCC_disclaimer [mm]
Fiducial10-20 [mm]
  round 1 smd mask+0.5: 1(0,0)
  Top Layer keep-out circle w1.178: c0,0 r0.5
Label_650x200 [mil] "Thermal Transfer Label"
  round 1 on Mech13: 0(0,0)
  silkscreen extent -325,-100 325,100, body extent -325,-100 325,100, height 1
MMB0207 [mm] "Vishay Beyschlag"
  rect 1.7x2.4 smd: 1(-2.45,0) 2(2.45,0)
  silkscreen extent -1.3,-1.1 1.3,1.1, body extent -2.98,-1.1 2.98,1.1, height 2.2
Molex_0022284023 [mm] "Header, 2.54mm, 2x1, TH"
  rect 1.55x1.55 hole 1.02: 1(-1.27,0)
  round 1.55 hole 1.02: 2(1.27,0)
  silkscreen extent -2.54,-1.24 2.54,1.5, body extent -2.54,-1.24 2.54,1.24, height 8.4
Pb-Free_Overlay_Small [mm]
  silkscreen extent -1.16,-1.17 1.17,1.17
RELAY_CPC1017N [mm] "SOP, 4-Lead, Body 4.089x3.81mm, Pitch 2.54mm"
  oval 1.3x0.6 smd: 1(-2.8,1.27) 2(-2.8,-1.27) 3(2.8,-1.27) 4(2.8,1.27)
  silkscreen extent -1.94,-2.15 1.94,2.4, body extent -1.94,-2.15 1.94,2.15, height 2.18
SMB-Bi [mm] "Molded Diode, 2-Leads, Body 5.4x3.6mm, IPC Medium Density, based on OnSemi component dimensions"
  rect 2.159x2.743 smd: 1(-2.21,0) 2(2.21,0)
  silkscreen extent -3.18,-1.99 3.18,1.99, body extent -2.65,-1.85 2.65,1.85, height 2.26
WL-SMCW_RED [mm] "WURTH"
  rect 0.8x0.8 smd: 1(-0.8,0) 2(0.8,0)
  silkscreen extent -1.9,-0.8 1.2,0.8, body extent -0.85,-0.45 0.85,0.45, height 0.8
WL-SMCW_YELLOW [mm] "WURTH"
  rect 0.8x0.8 smd: 1(-0.8,0) 2(0.8,0)
  silkscreen extent -1.9,-0.8 1.2,0.8, body extent -0.85,-0.45 0.85,0.45, height 0.8
Wurth_60900213421 [mil] "Shunt, 2.54mm, Black"
  round 1 on Mech3: 0(0,0)
  body extent -98,-48 98,48, height 236
Wurth_61301011121 [mm] "Header, 2.54mm, 10x1, TH"
  rect 1.6x1.6 hole 1.1: 1(-11.43,0)
  round 1.6 hole 1.1: 2(-8.89,0) 3(-6.35,0) 4(-3.81,0) 5(-1.27,0) 6(1.27,0) 7(3.81,0) 8(6.35,0) 9(8.89,0) 10(11.43,0)
  silkscreen extent -12.7,-1.27 12.7,1.6, body extent -12.7,-1.27 12.7,1.27, height 8.54
Wurth_691356310010B [mm] "Header, 3.81mm, 5x2, TH"
  rrect50% 2.1x2.1 hole 1.4: 1(-6.35,7.62)
  round 2.1 hole 1.4: 2(6.35,7.62) 3(-6.35,3.81) 4(6.35,3.81) 5(-6.35,0) 6(6.35,0) 7(-6.35,-3.81) 8(6.35,-3.81) 9(-6.35,-7.62) 10(6.35,-7.62)
  silkscreen extent -14.35,-9.92 7.55,10.6, body extent -14.35,-9.92 7.55,9.92, height 22.5
YZF0004-C01 [mm] "BGA, 4-Balls, Body 1.062x1.116mm, Pitch 0.5mm"
  round 0.245 smd paste-0.125: A1(-0.25,0.25) A2(0.25,0.25) B1(-0.25,-0.25) B2(0.25,-0.25)
  silkscreen extent -0.68,-0.65 0.67,0.65, body extent -0.57,-0.55 0.57,0.55, height 0.63

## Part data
C1 C2 C3 C5_DI1 C5_DI2 C5_DI3 C5_DI4 C5_DI5 C5_DI6 C8_Ch7-8 C8_Ch9-10 C9_Ch7-8 C9_Ch9-10: "CAP, CERM, 0.1 µF, 50 V,+/- 10%, X7R, 0603", Cap_Case=0603, Manufacturer=MuRata, Supplier Part Number 1=490-1519-1-ND, TempCo=X7R, Tolerance_%=10, Value2=50V, ValueDisplayed=0.1µF
C4: "CAP, CERM, 2200 pF, 2000 V,+/- 10%, X7R, 1210", Cap_Case=1210, Manufacturer="Johanson Technology", Supplier Part Number 1=709-1307-1-ND, TempCo=X7R, Tolerance_%=10, Value2=2000V, ValueDisplayed=2200pF
C6_DI1 C6_DI2 C6_DI3 C6_DI4 C6_DI5 C6_DI6 C7_DI1 C7_DI2 C7_DI3 C7_DI4 C7_DI5 C7_DI6 C10_Ch7-8 C10_Ch9-10 C11_Ch7-8 C11_Ch9-10: "CAP, CERM, 0.01 µF, 50 V,+/- 10%, X7R, AEC-Q200 Grade 1, 0402", Cap_Case=0402, Manufacturer=TDK, Supplier Part Number 1=445-6893-1-ND, TempCo=X7R, Tolerance_%=10, Value1="0.333065 ohm", Value2=50V, ValueDisplayed=0.01µF
D1 D3: "LED, Red, SMD", Color=Red, Manufacturer="Wurth Elektronik", Power_TotalModule=0.072, Supplier Part Number 1=732-4978-1-ND, Value1=0.072W, Value2=2V
D2 D4: "Diode, TVS, Bi, 36 V, 64.3 Vc, SMB", Manufacturer=STMicroelectronics, Supplier Part Number 1=497-6496-1-ND, Value1=W
D5_DI1 D5_DI2 D5_DI3 D5_DI4 D5_DI5 D5_DI6 D6_DI1 D6_DI2 D6_DI3 D6_DI4 D6_DI5 D6_DI6 D9_Ch7-8 D9_Ch9-10 D11_Ch7-8 D11_Ch9-10: library part CMP-0076768-1, "ChipGuard Automotive MLA Series Varistor ESD Clamp Protectors", Manufacturer=Bourns, Supplier Part Number 1=CGA0603MLA-31900E-ND
D7_DI1 D7_DI2 D7_DI3 D7_DI4 D7_DI5 D7_DI6 D8_DI1 D8_DI2 D8_DI3 D8_DI4 D8_DI5 D8_DI6 D10_Ch7-8 D10_Ch9-10 D12_Ch7-8 D12_Ch9-10: "LED, Yellow, SMD", Color=yellow, Manufacturer="Wurth Elektronik", Supplier Part Number 1=732-4981-1-ND, Value1=W, Value2=2V
FID1 FID2 FID3 FID4 FID5 FID6: "Fiducial mark.  There is nothing to buy or mount.", Manufacturer=N/A
J1 J2 J3 J4: "Connector, Receptacle, 100mil, 10x1, Gold plated, TH", Manufacturer=Samtec
J5 J8: "Header, 2.54mm, 10x1, Gold, TH", Color=Black, Manufacturer="Wurth Elektronik", Supplier Part Number 1=732-2670-ND
J6 J9: library part CMP-0077239-1, "Header, 3.81mm, 5x2, R/A, Tin, TH", Color="Light Green", Current_A=10A, Manufacturer="Wurth Elektronik", Voltage_V=300V
J7 J10: "Header, 2.54mm, 2x1, Tin, TH", Color=Black, Current_A=4, Manufacturer=Molex, Supplier Part Number 1=WM50016-02-ND, Voltage_V=250
K1 K2: "Relay, SPST-NC (1 Form B), 0.15 A, SMD", Contact Rating_A=0.15, Manufacturer=IXYS, Supplier Part Number 1=CPC1117N-ND
LBL1: library part THT-14-423-10, "Thermal Transfer Printable Labels, 0.650\" W x 0.200\" H - 10,000 per roll", Manufacturer=Brady, Supplier Part Number 1=97C5133
Logo2: library part Pb-Free
Logo3: library part FCC_disclaimer, "FCC_disclaimer"
R1 R5 R7 R8: "RES, 100, 1%, 0.1 W, 0603", Manufacturer=Vishay-Dale, Power_W=0.1, Supplier Part Number 1=541-100HCT-ND, TempCo="100 ppm/C", Tolerance_%=1, Value1=1%, Value2=0.1W, Value_Code=100R, ValueDisplayed=100
R2 R3: "RES, 47, 5%, 0.1 W, 0603", Manufacturer=Vishay-Dale, Power_W=0.1, Supplier Part Number 1=541-47GCT-ND, TempCo="200 ppm/C", Tolerance_%=5, Value1=5%, Value2=0.1W, Value_Code=47R0, ValueDisplayed=47
R4 R6: "RES, 0, 5%, 0.1 W, 0603", Manufacturer=Vishay-Dale, Power_W=0.1, Supplier Part Number 1=541-0.0GCT-ND, TempCo="200 ppm/C", Tolerance_%=5, Value1=5%, Value2=0.1W, Value_Code=0000, ValueDisplayed=0
R9_DI1 R9_DI2 R9_DI3 R9_DI4 R9_DI5 R9_DI6 R11_DI1 R11_DI2 R11_DI3 R11_DI4 R11_DI5 R11_DI6 R15_Ch7-8 R15_Ch9-10 R18_Ch7-8 R18_Ch9-10: library part CMP-0076703-1, "RES, 2.49 k, 1%, 1 W, AEC-Q200 Grade 0, 2.2x5.8mm", Manufacturer=Vishay/Beyschlag, Power_W=1W, Supplier Part Number 1=MMB-2.49KBCT-ND, TempCo="50 ppm/C", Tolerance_%=1%, Value_Code=2k49, ValueDisplayed=2.49k
R10_DI1 R10_DI2 R10_DI3 R10_DI4 R10_DI5 R10_DI6 R12_DI1 R12_DI2 R12_DI3 R12_DI4 R12_DI5 R12_DI6 R16_Ch7-8 R16_Ch9-10 R19_Ch7-8 R19_Ch9-10: "RES, 562, 1%, 0.063 W, 0402", Manufacturer=Vishay-Dale, Power_W=0.063, Supplier Part Number 1=541-562LCT-ND, TempCo="100 ppm/C", Tolerance_%=1, Value1=1%, Value2=0.063W, Value_Code=562R, ValueDisplayed=562
R13_DI1 R13_DI2 R13_DI3 R13_DI4 R13_DI5 R13_DI6 R14_DI1 R14_DI2 R14_DI3 R14_DI4 R14_DI5 R14_DI6 R17_Ch7-8 R17_Ch9-10 R20_Ch7-8 R20_Ch9-10: "RES, 750, 1%, 0.1 W, 0603", Manufacturer=Vishay-Dale, Power_W=0.1, Supplier Part Number 1=541-750HCT-ND, TempCo="100 ppm/C", Tolerance_%=1, Value1=1%, Value2=0.1W, Value_Code=750R, ValueDisplayed=750
SH-J1 SH-J2: "Shunt, 2.54mm, Gold, Black", Manufacturer="Wurth Elektronik", Supplier Part Number 1=732-2678-ND
U1 U2: "Parallel-Load 8-Bit Shift Registers, D0016A, TUBE", Alternate Manufacturer="Texas Instruments", Alternate PartNumber=Equivalent, F @ Nom Voltage(Max)(Mhz)=70, Generic Part Number=SN74LV165A, ICC @ Nom Voltage(Max)(mA)=0.02, Operating Temperature Range(C)="-40 to 125", Rating=Catalog, tpd @ Nom Voltage(Max)(ns)="28, 16.9, 13.5", Voltage(Nom)(V)="2.5, 3.3, 5"
U3: library part CMP-0051656-1, "Single Inverter Gate, DBV0005A, LARGE T&R", F @ Nom Voltage(Max)(Mhz)=150, Generic Part Number=SN74LVC1GU04, ICC @ Nom Voltage(Max)(mA)=0.01, Manufacturer="Texas Instruments", Operating Temperature Range(C)="-40 to 125,-40 to 85", Rating=Catalog, tpd @ Nom Voltage(Max)(ns)=5.5,4.5,4.2,3.5, Voltage(Nom)(V)=1.8,2.5,3.3,5
U4_DI1 U4_DI2 U4_DI3 U4_DI4 U4_DI5 U4_DI6 U6_DI1 U6_DI2 U6_DI3 U6_DI4 U6_DI5 U6_DI6 U7_DI1 U7_DI2 U7_DI3 U7_DI4 U7_DI5 U7_DI6 U8_DI1 U8_DI2 U8_DI3 U8_DI4 U8_DI5 U8_DI6 U10_Ch7-8 U10_Ch9-10 U11_Ch7-8 U11_Ch9-10 U13_Ch7-8 U13_Ch9-10 U14_Ch7-8 U14_Ch9-10: "33V Precision Surge Protection Clamp, YZF0004-C01 (DSBGA-4)", Alternate Manufacturer="Texas Instruments", Alternate PartNumber=TVS3300YZFT
U5_DI1 U5_DI2 U5_DI3 U5_DI4 U5_DI5 U5_DI6: "ISO1212DBQR, DBQ00016A, DBQ0016A (SSOP-16)", Alternate Manufacturer="Texas Instruments", Alternate PartNumber=ISO1212DBQ
U9_Ch7-8 U9_Ch9-10 U12_Ch7-8 U12_Ch9-10: library part CMP-0013019-2, "ISO1211DR, D0008B (SOIC-8)", Alternate Manufacturer="Texas Instruments", Alternate PartNumber=ISO1211D
ZZ1: library part AssemblyNoteLabel
ZZ2 ZZ3 ZZ4: library part AssemblyNote

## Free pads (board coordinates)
  round 2.5 hole 2.5 unplated mask+0.254: 1(2.52,2.52) 1(2.52,100.3) 1(55.9,2.52) 1(55.9,100.3)

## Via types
v1: diameter 0.5, hole 0.2, Top Layer to Bottom Layer, 129 vias
v2: diameter 0.7, hole 0.4, Top Layer to Bottom Layer, 1 vias

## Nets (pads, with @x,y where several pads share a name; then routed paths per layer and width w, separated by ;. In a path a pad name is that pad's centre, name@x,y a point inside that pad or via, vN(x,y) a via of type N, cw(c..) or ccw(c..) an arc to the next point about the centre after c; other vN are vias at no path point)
3V3: C1.1 C2.1 C3.1 C5_DI1.1 C5_DI2.1 C5_DI3.1 C5_DI4.1 C5_DI5.1 C5_DI6.1 C8_Ch7-8.1 C8_Ch9-10.1 C9_Ch7-8.1 C9_Ch9-10.1 J1.1 U1.16 U2.16 U3.5 U5_DI1.2 U5_DI1.3 U5_DI2.2 U5_DI2.3 U5_DI3.2 U5_DI3.3 U5_DI4.2 U5_DI4.3 U5_DI5.2 U5_DI5.3 U5_DI6.2 U5_DI6.3 U9_Ch7-8.1 U9_Ch7-8.2 U9_Ch9-10.1 U9_Ch9-10.2 U12_Ch7-8.1 U12_Ch7-8.2 U12_Ch9-10.1 U12_Ch9-10.2 | length 63.6
  Top Layer w0.2: U5_DI1.2@14.45,61.74 15.082,61.74 U5_DI1.3@15.148,61.675 15.148,60.173 C5_DI1.1@14.775,59.8 ; U5_DI1.2@14.513,61.675 14.513,60.063 C5_DI1.1@14.775,59.8 ; v1(15.7,59.8) C5_DI1.1@14.775,59.8 ; U5_DI2.2@23.55,61.74 24.182,61.74 U5_DI2.3@24.248,61.675 24.248,60.173 C5_DI2.1@23.875,59.8 ; U5_DI2.2@23.613,61.675 23.613,60.063 C5_DI2.1@23.875,59.8 ; v1(24.8,59.8) C5_DI2.1@23.875,59.8 ; U1.16@26.225,35.195 26.225,36.075 C1.1@25.3,37 v1(26.25,37) ; U5_DI3.2@32.65,61.74 33.282,61.74 U5_DI3.3@33.348,61.675 33.347,60.173 C5_DI3.1@32.975,59.8 ; U5_DI3.2@32.713,61.675 32.712,60.063 C5_DI3.1@32.975,59.8 ; v1(33.9,59.8) C5_DI3.1@32.975,59.8 ; v1(37.5,38.5) 36.8,38.5 C2.1@36.55,38.75 36.425,38.625 U2.16@36.425,36.945 v1(37.655,36.945) ; v1(40.375,37.875) U3.5@40.375,37.05 40.375,35.575 C3.1@40.7,35.25 v1(40.7,34.2) ; U9_Ch7-8.1@41.195,61.75 U9_Ch7-8.2@42.465,61.75 42.465,60.235 C8_Ch7-8.1@42.9,59.8 42.9,59.1 v1(42.5,58.7) ; U12_Ch7-8.1@46.495,61.75 U12_Ch7-8.2@47.765,61.75 47.765,60.235 C9_Ch7-8.1@48.2,59.8 48.2,59.1 v1(47.7,58.6)
  Bottom Layer w0.2: v1(15.7,59.8) C5_DI6.1@16.6,59.8 ; v1(24.8,59.8) C5_DI5.1@25.7,59.8 ; v1(33.9,59.8) C5_DI4.1@34.8,59.8 ; v1(42.5,58.7) 42,59.2 C9_Ch9-10.1@42,59.8 42.435,60.235 U12_Ch9-10.2@42.435,61.75 U12_Ch9-10.1@43.705,61.75 ; v1(47.7,58.6) 47.4,58.9 C8_Ch9-10.1@47.4,59.8 47.735,60.135 U9_Ch9-10.2@47.735,61.75 U9_Ch9-10.1@49.005,61.75 ; C5_DI6.1@16.6,59.8 16.862,60.062 U5_DI6.2@16.862,61.675 U5_DI6.3@16.227,61.675 16.227,60.173 C5_DI6.1@16.6,59.8 ; C5_DI5.1@25.7,59.8 25.962,60.062 25.962,61.675 25.327,61.675 25.327,60.173 C5_DI5.1@25.7,59.8 ; C5_DI4.1@34.8,59.8 35.062,60.062 U5_DI4.2@35.062,61.675 U5_DI4.3@34.427,61.675 34.427,60.173 C5_DI4.1@34.8,59.8
5V: J3.1
BrWi1-8: J2.2 R1.1 | length 20
  Top Layer w0.2: J2.2@52.07,39.37 54,41.3 54,46 52.9,47.1 R1.1@52.9,58.15
BrWi9-16: J1.8 R5.1 | length 36.8
  Top Layer w0.2: R5.1@5.7,58.2 4,56.5 4,24.6 4.47,24.13 J1.8@6.35,24.13
DGND: C1.2 C2.2 C3.2 C5_DI1.2 C5_DI2.2 C5_DI3.2 C5_DI4.2 C5_DI5.2 C5_DI6.2 C8_Ch7-8.2 C8_Ch9-10.2 C9_Ch7-8.2 C9_Ch9-10.2 D7_DI1.1 D7_DI2.1 D7_DI3.1 D7_DI4.1 D7_DI5.1 D7_DI6.1 D8_DI1.1 D8_DI2.1 D8_DI3.1 D8_DI4.1 D8_DI5.1 D8_DI6.1 D10_Ch7-8.1 D10_Ch9-10.1 D12_Ch7-8.1 D12_Ch9-10.1 J2.1 J3.2 J5.1 J8.1 K1.2 K2.2 R7.1 R8.1 U1.8 U1.10 U1.15 U2.8 U2.15 U3.3 U5_DI1.1 U5_DI1.8 U5_DI2.1 U5_DI2.8 U5_DI3.1 U5_DI3.8 U5_DI4.1 U5_DI4.8 U5_DI5.1 U5_DI5.8 U5_DI6.1 U5_DI6.8 U9_Ch7-8.4 U9_Ch9-10.4 U12_Ch7-8.4 U12_Ch9-10.4 | length 72.7
  Top Layer w0.2: v1(12.1,59.8) C5_DI1.2@13.175,59.8 ; v1(12.4,55.2) D8_DI1.1@14.9,55.2 ; v1(17.55,36.8) R8.1@18.8,36.8 v1(19.855,36.8) ; U5_DI1.8@18.323,61.675 v1(19.375,61.675) ; v1(19.495,26.305) U1.8@20.775,26.305 ; v1(21.2,59.8) C5_DI2.2@22.275,59.8 ; v1(21.5,55.2) D8_DI2.1@24,55.2 ; v1(22.75,37) C1.2@23.7,37 ; U1.10@26.225,27.575 v1(27.475,27.575) ; U1.15@26.225,33.925 26.25,33.9 v1(27.5,33.9) ; U5_DI2.8@27.423,61.675 v1(28.475,61.675) ; v1(29.745,28.055) U2.8@30.975,28.055 ; v1(30.3,59.8) C5_DI3.2@31.375,59.8 ; v1(30.6,55.2) D8_DI3.1@33.1,55.2 ; R7.1@32.5,40.5 v1(33.5,40.5) ; v1(34,38.75) C2.2@34.95,38.75 ; U2.15@36.425,35.675 v1(37.625,35.675) ; U5_DI3.8@36.523,61.675 v1(37.575,61.675) ; v1(42.3,34.2) C3.2@42.3,35.25 42,35.55 42,38.75 42.2,38.95 U3.3@43.125,38.95 v1(43.125,40.125) ; v1(44.1,55.2) D10_Ch7-8.1@45.3,55.2 ; U9_Ch7-8.4@45.005,61.75 45.005,60.305 C8_Ch7-8.2@44.5,59.8 44.5,59.1 44.9,58.7 v1(45.2,58.7) ; v1(49.3,55.2) D12_Ch7-8.1@50.6,55.2 ; U12_Ch7-8.4@50.305,61.75 50.305,60.305 C9_Ch7-8.2@49.8,59.8 v1(50.8,59.8)
  Top Layer w0.3: K2.2@8.27,61.7 v1(9,61.7) ; K1.2@55.27,61.6 v1(56,61.6)
  Top Layer w0.4: v1(12.125,61.675) U5_DI1.1@13.878,61.675 ; v1(21.225,61.675) U5_DI2.1@22.978,61.675 ; v1(30.325,61.675) U5_DI3.1@32.078,61.675
  Bottom Layer w0.2: v1(12.125,61.675) U5_DI6.8@13.052,61.675 ; U5_DI6.1@17.497,61.675 17.497,60.503 C5_DI6.2@18.2,59.8 v1(19.4,59.8) ; v1(21.225,61.675) U5_DI5.8@22.152,61.675 ; U5_DI5.1@26.597,61.675 26.597,60.503 C5_DI5.2@27.3,59.8 v1(28.5,59.8) ; v1(30.325,61.675) U5_DI4.8@31.252,61.675 ; v1(37.575,61.675) U5_DI4.1@35.697,61.675 35.697,60.503 C5_DI4.2@36.4,59.8 v1(37.6,59.8) ; v1(39.4,59.8) C9_Ch9-10.2@40.4,59.8 39.895,60.305 U12_Ch9-10.4@39.895,61.75 ; D12_Ch9-10.1@42.9,55.2 v1(44.1,55.2) ; U9_Ch9-10.4@45.195,61.75 45.195,60.405 C8_Ch9-10.2@45.8,59.8 45.8,59.1 45.4,58.7 v1(45.2,58.7) ; D10_Ch9-10.1@47.9,55.2 v1(49.3,55.2)
  other v1: 17,43.75 20.75,43.75 23,43.75 25.25,43.75 27.5,43.75 31.25,43.75 33,43.75 35.5,43.75 38,43.75 40.75,43.75 18.75,44.25
FGND: C4.1 C6_DI1.1 C6_DI2.1 C6_DI3.1 C6_DI4.1 C6_DI5.1 C6_DI6.1 C7_DI1.1 C7_DI2.1 C7_DI3.1 C7_DI4.1 C7_DI5.1 C7_DI6.1 C10_Ch7-8.1 C10_Ch9-10.1 C11_Ch7-8.1 C11_Ch9-10.1 D2.1 D4.1 D5_DI1.1 D5_DI2.1 D5_DI3.1 D5_DI4.1 D5_DI5.1 D5_DI6.1 D6_DI1.1 D6_DI2.1 D6_DI3.1 D6_DI4.1 D6_DI5.1 D6_DI6.1 D9_Ch7-8.1 D9_Ch9-10.1 D11_Ch7-8.1 D11_Ch9-10.1 J6.10 J7.1 J9.2 J10.1 K1.3 K2.3 U6_DI1.A1 U6_DI1.A2 U6_DI2.A1 U6_DI2.A2 U6_DI3.A1 U6_DI3.A2 U6_DI4.A1 U6_DI4.A2 U6_DI5.A1 U6_DI5.A2 U6_DI6.A1 U6_DI6.A2 U8_DI1.A1 U8_DI1.A2 U8_DI2.A1 U8_DI2.A2 U8_DI3.A1 U8_DI3.A2 U8_DI4.A1 U8_DI4.A2 U8_DI5.A1 U8_DI5.A2 U8_DI6.A1 U8_DI6.A2 U11_Ch7-8.A1 U11_Ch7-8.A2 U11_Ch9-10.A1 U11_Ch9-10.A2 U14_Ch7-8.A1 U14_Ch7-8.A2 U14_Ch9-10.A1 U14_Ch9-10.A2 | length 122.9
  Top Layer w0.2: v1(12,71) v1(15.7,71) v1(19.4,71) v1(21.1,71) v1(24.8,71) v1(28.5,71) v1(33.9,71) D6_DI3.1@36.6,71 ; C7_DI3.1@36.6,70 C7_DI3.1@36.8,70 ; D6_DI3.1@36.6,71.34 D6_DI3.1@36.6,71 ; D9_Ch7-8.1@43.1,71.34 D9_Ch7-8.1@43.1,71 ; D11_Ch7-8.1@48.3,71.34 D11_Ch7-8.1@48.3,71 ; v1(49.7,71) D11_Ch7-8.1@48.3,71 ; D6_DI3.1@36.6,71 v1(37.6,71) v1(40.7,71) D9_Ch7-8.1@43.1,71 ; D9_Ch7-8.1@43.1,71 v1(45.1,71) D11_Ch7-8.1@48.3,71
  Top Layer w0.3: C6_DI1.1@14.8,70 14.8,70.45 ; C7_DI1.1@18.6,70 18.6,70.45 ; C6_DI2.1@23.9,70 23.9,70.45 ; C7_DI2.1@27.7,70 27.7,70.45 ; C6_DI3.1@33,70 33,70.45 ; C7_DI3.1@36.8,70 36.8,70.45 ; C10_Ch7-8.1@43.1,70 43.1,70.55 ; C11_Ch7-8.1@48.3,70 48.3,70.45
  Top Layer w0.4: J10.1@8.22,69.5 8.27,69.45 K2.3@8.27,67.3
  Top Layer w0.5: 8.95,84.25 J6.10@11.63,84.25 ; J9.2@46.87,84.25 49.25,84.25 ; 53.5,91.2 C4.1@53.5,92.35 ; K1.3@55.27,67.2 J7.1@55.27,69.4 55.27,70.57 56.21,71.51 D2.1@56.21,73.3 56.21,75.69
  GND w0.5: 7.65,84.25 J6.10@11.63,84.25 ; J9.2@46.87,84.25 50.45,84.25
  VCC w0.5: 8.8,84.25 J6.10@11.63,84.25 ; J9.2@46.87,84.25 51.15,84.25
  Bottom Layer w0.2: v1(12,71) v1(15.7,71) v1(19.4,71) v1(21.1,71) v1(24.8,71) v1(28.5,71) v1(33.9,71) v1(37.6,71) v1(40.7,71) 41.9,71 v1(45.1,71) 47.1,71 v1(49.7,71)
  Bottom Layer w0.3: C7_DI6.1@12.775,70 12.775,70.5 ; C6_DI6.1@16.575,70 16.575,70.55 ; C7_DI5.1@21.875,70 21.875,70.5 ; C6_DI5.1@25.675,70 25.675,70.45 ; C7_DI4.1@30.975,70 30.975,70.521 ; C6_DI4.1@34.775,70 34.775,70.521 ; C11_Ch9-10.1@41.9,70 41.9,71 D11_Ch9-10.1@41.9,71.34 ; C10_Ch9-10.1@47.1,70 47.1,71 D9_Ch9-10.1@47.1,71.34
  Bottom Layer w0.5: 8.95,84.25 J6.10@11.63,84.25 ; J9.2@46.87,84.25 49.02,84.25
  other v1: 30.227,71.006 51.7,71.2 53.7,71.2 40.7,71.7 45.1,71.7 49.7,71.7 12,71.8 15.7,71.8 19.4,71.8 21.1,71.8 24.8,71.8 28.5,71.8 30.227,71.806 33.9,71.8 37.6,71.8
FGND_float1-8: D2.2 J7.2 K1.4 U5_DI1.9 U5_DI1.14 U5_DI2.9 U5_DI2.14 U5_DI3.9 U5_DI3.14 U9_Ch7-8.6 U12_Ch7-8.6 | length 56.1
  Top Layer w0.3: 15.148,65.948 U5_DI1.14@15.148,67.125 ; 18.323,66.023 U5_DI1.9@18.323,67.125 ; 24.248,66.048 U5_DI2.14@24.248,67.125 ; 27.423,66.023 U5_DI2.9@27.423,67.125 ; 33.348,66.048 U5_DI3.14@33.348,67.125 ; 36.523,66.023 U5_DI3.9@36.523,67.125 ; 43.735,66.035 U9_Ch7-8.6@43.735,67.25 ; 49.035,66.035 U12_Ch7-8.6@49.035,67.25
  Top Layer w0.5: 15.2,65.9 52.3,65.9 52.73,66.33 K1.4@52.73,67.2 J7.2@52.73,69.4 ; D2.2@51.79,73.3 v2(53.7,73.3)
  VCC w0.5: J7.2@52.73,69.4 52.73,72.33 v2(53.7,73.3)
